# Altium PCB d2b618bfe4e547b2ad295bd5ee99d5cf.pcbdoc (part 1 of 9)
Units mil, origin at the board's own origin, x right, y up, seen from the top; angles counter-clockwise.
Board outline 5129 x 4161 mil, 8 copper layers (Top Layer, GND1, 内层2, VCC, 内层4, Inner5, GND2, Bottom Layer); 491 components, 452 nets, 2562 pads, 1124 vias.
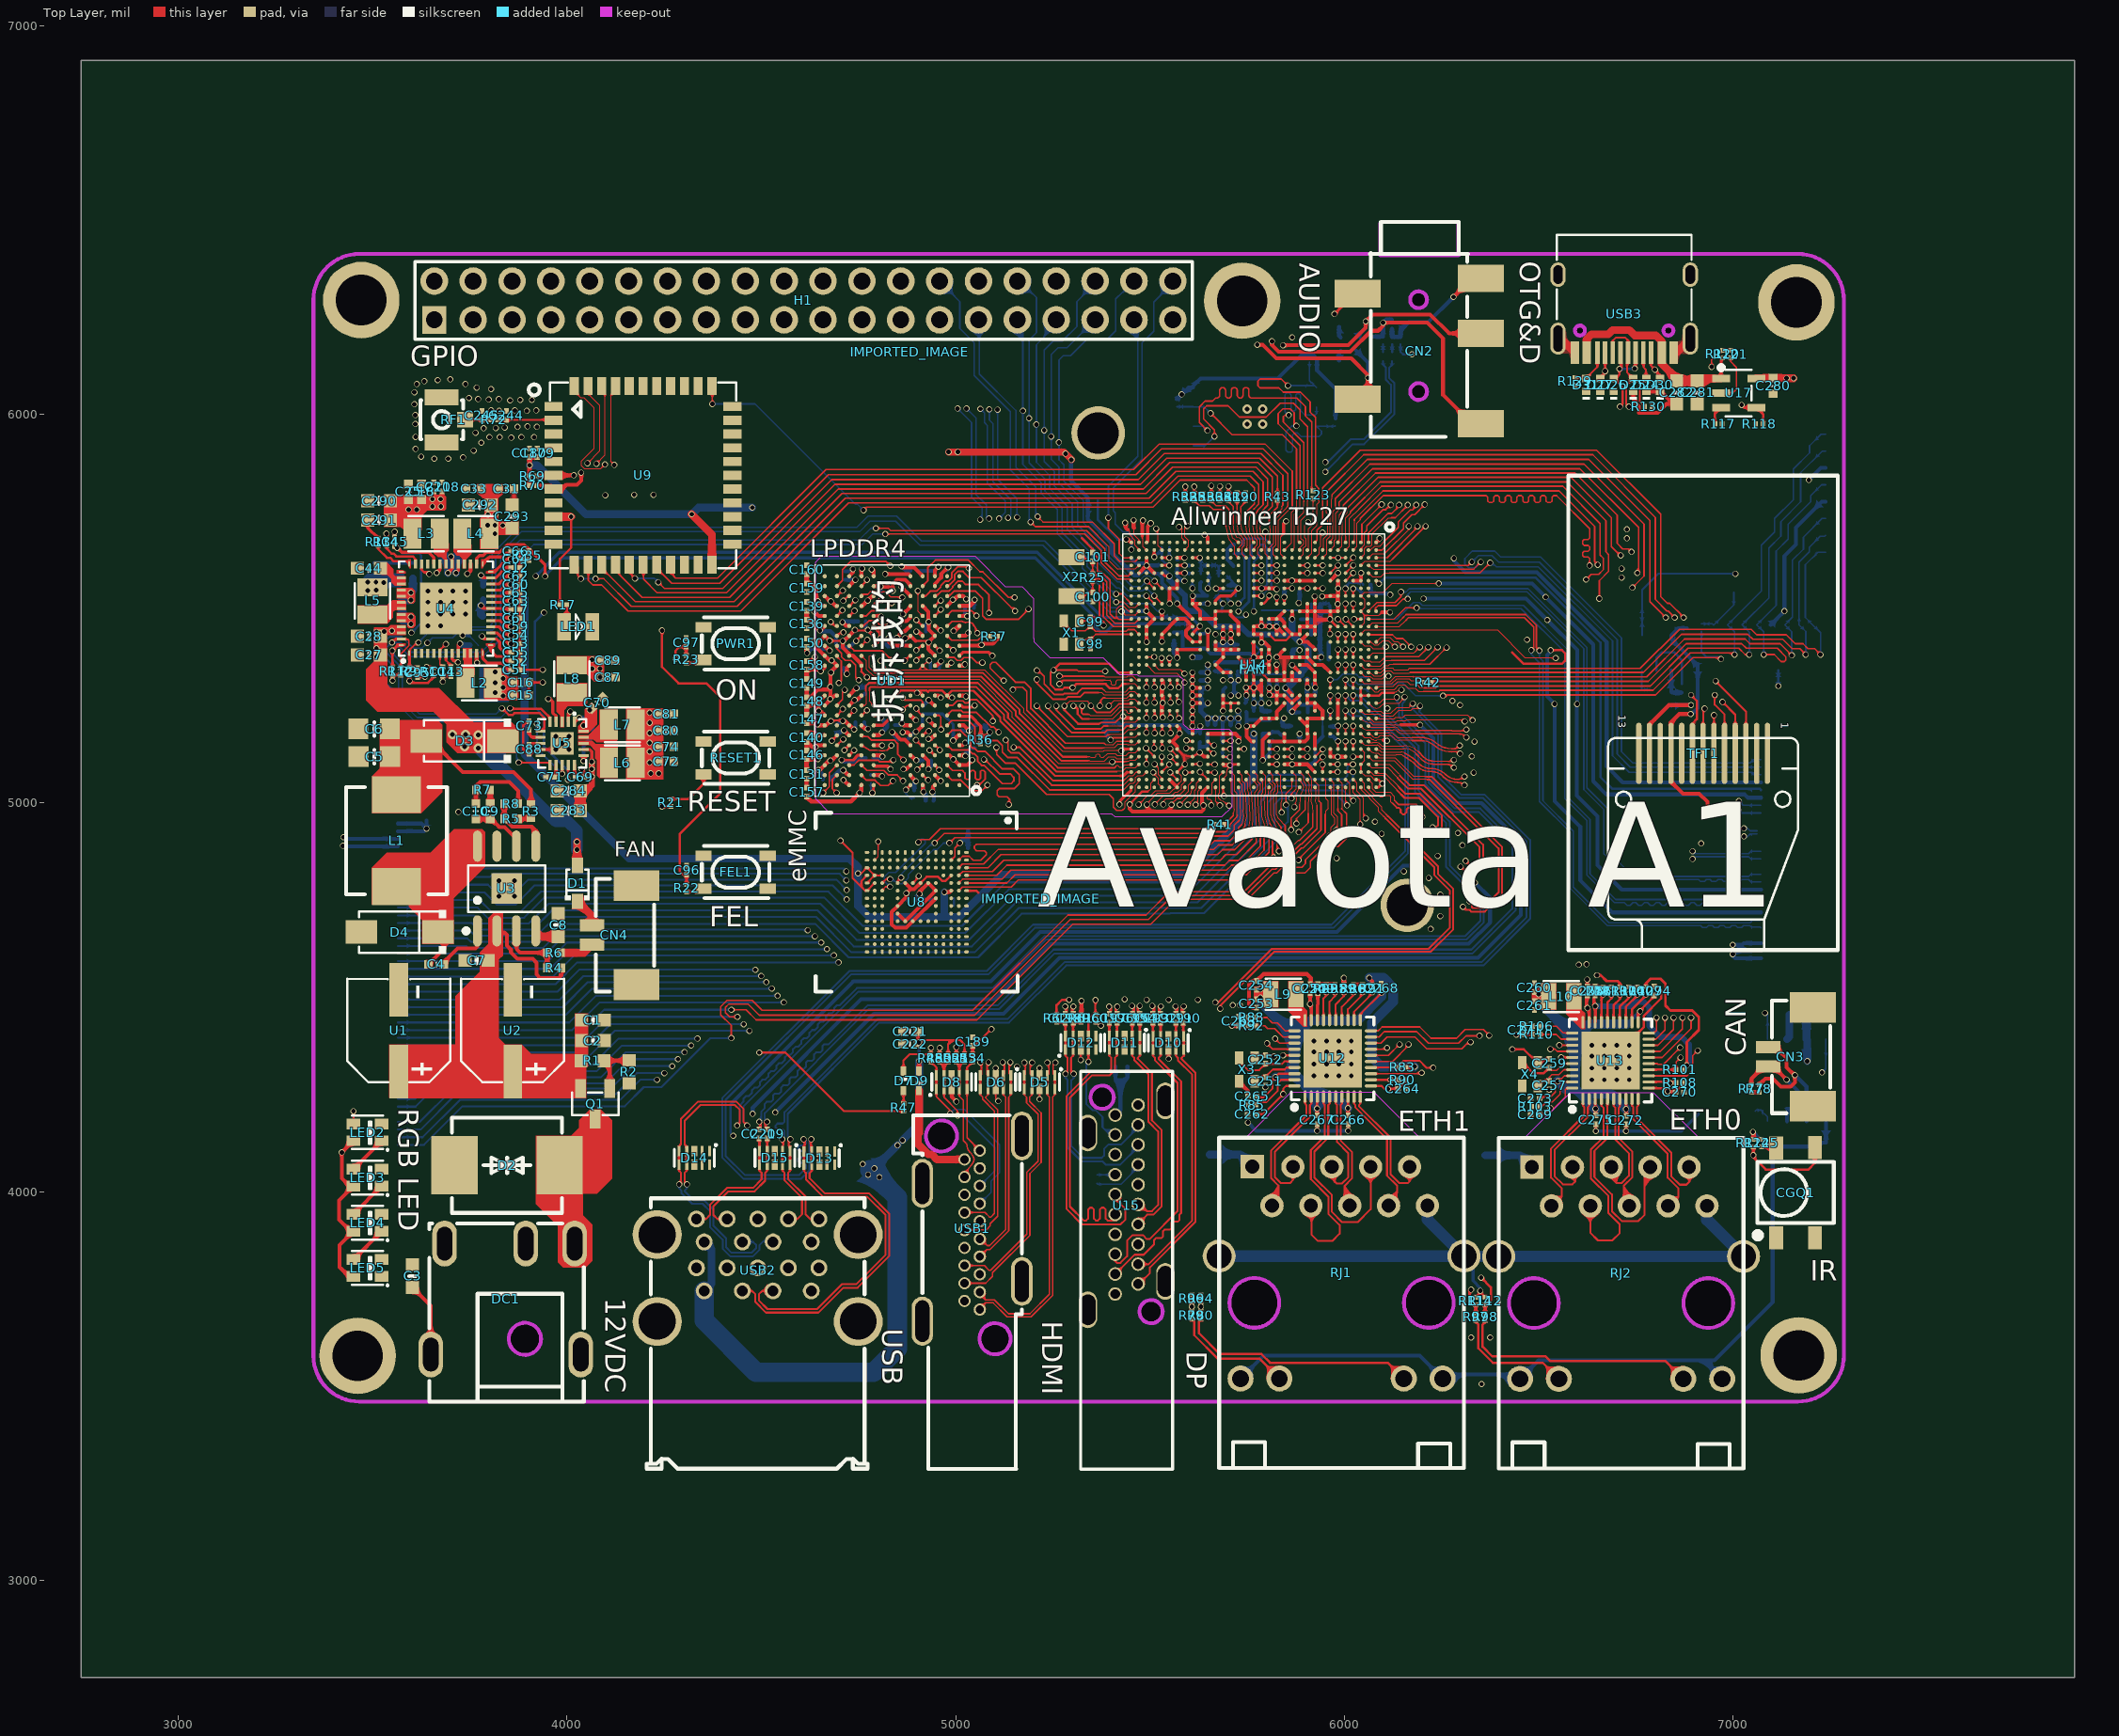
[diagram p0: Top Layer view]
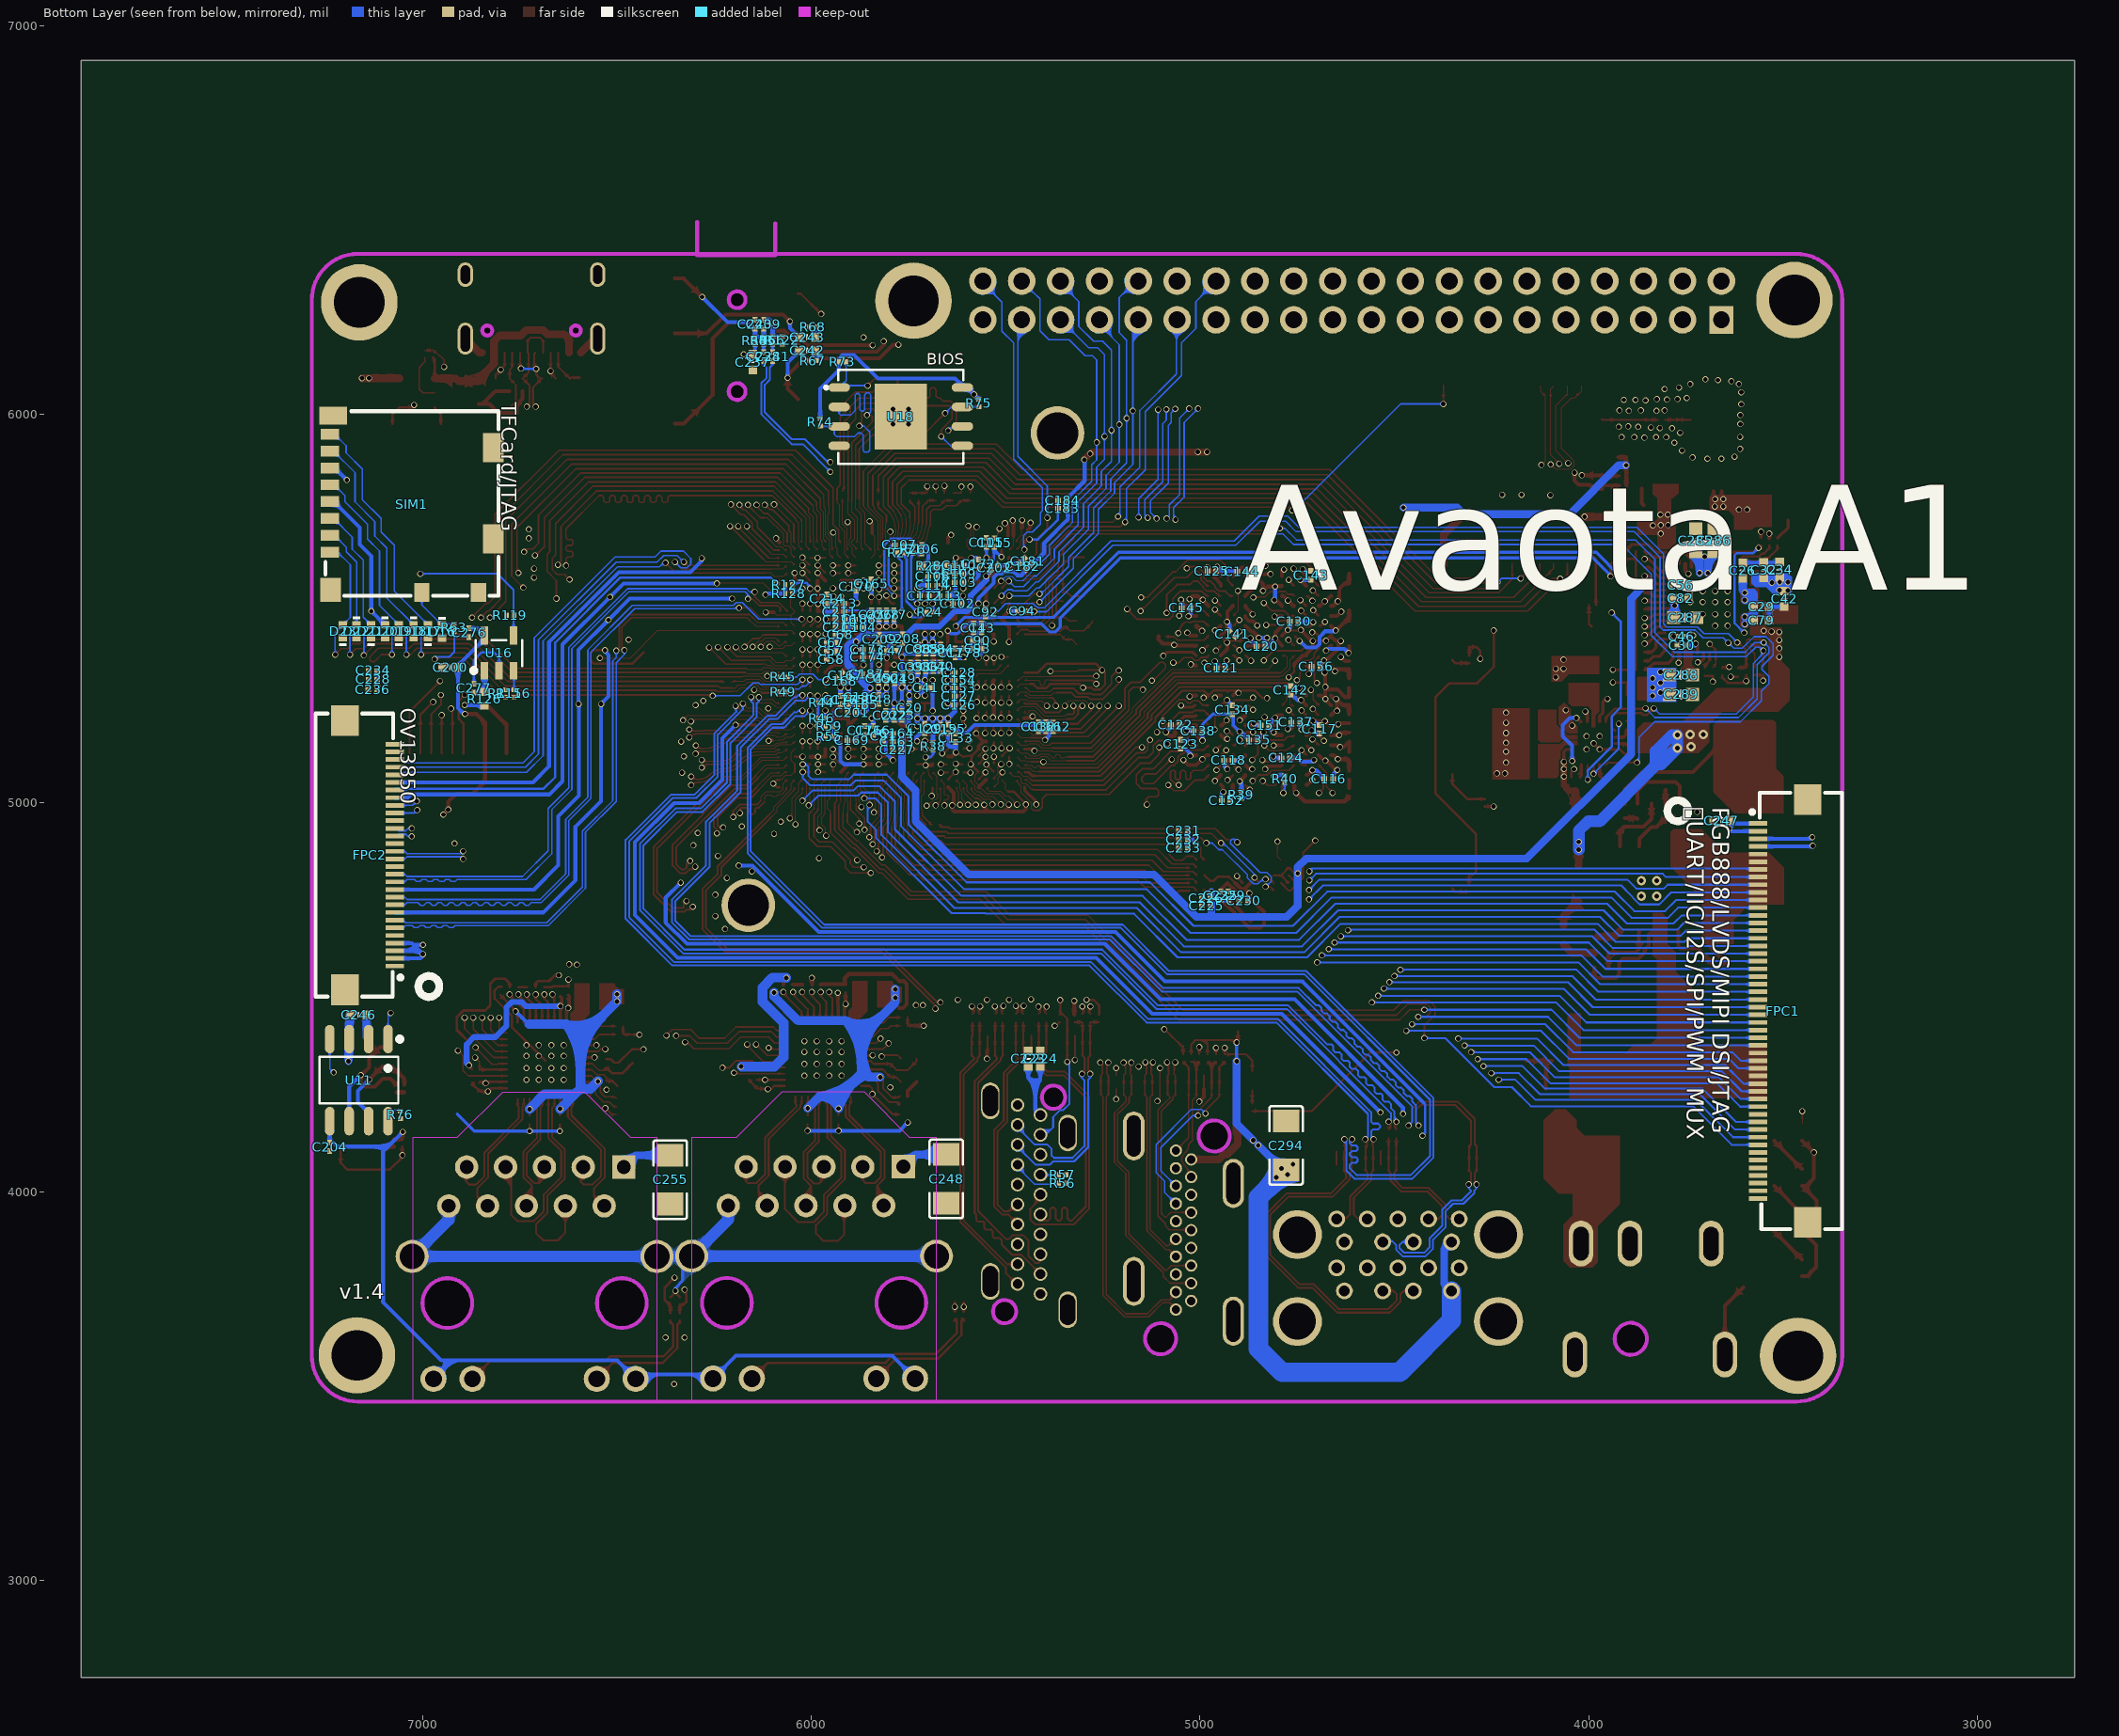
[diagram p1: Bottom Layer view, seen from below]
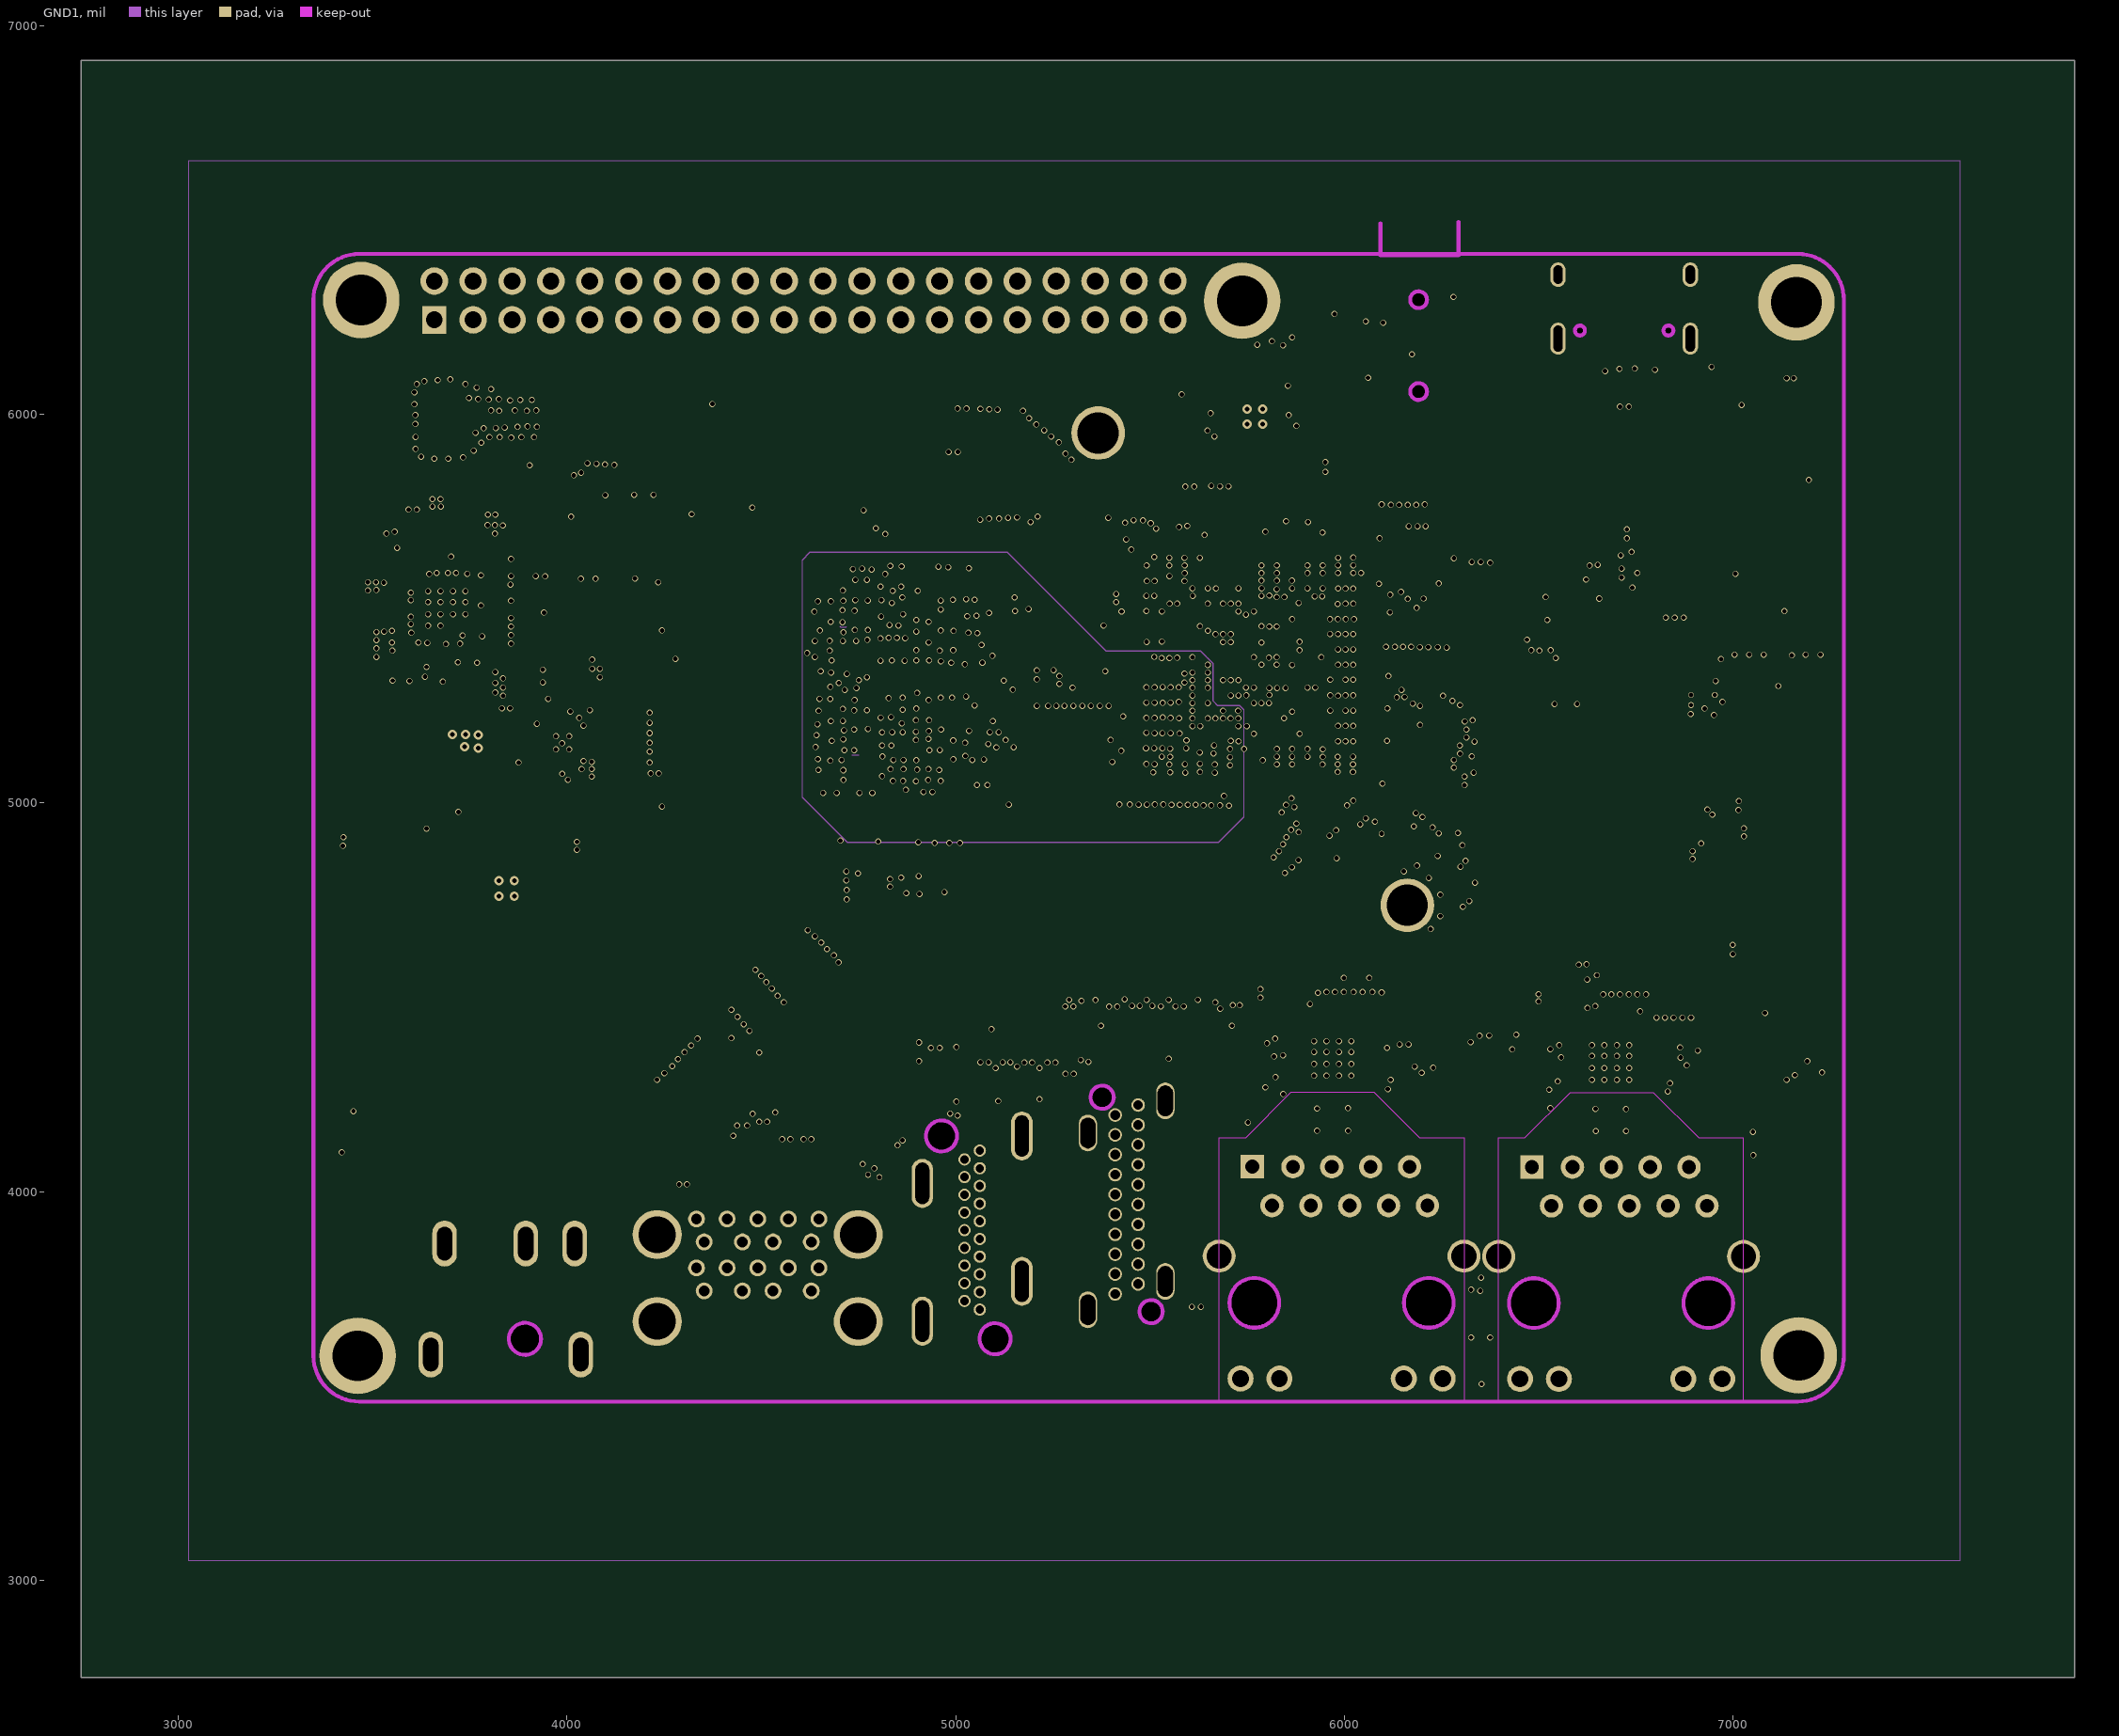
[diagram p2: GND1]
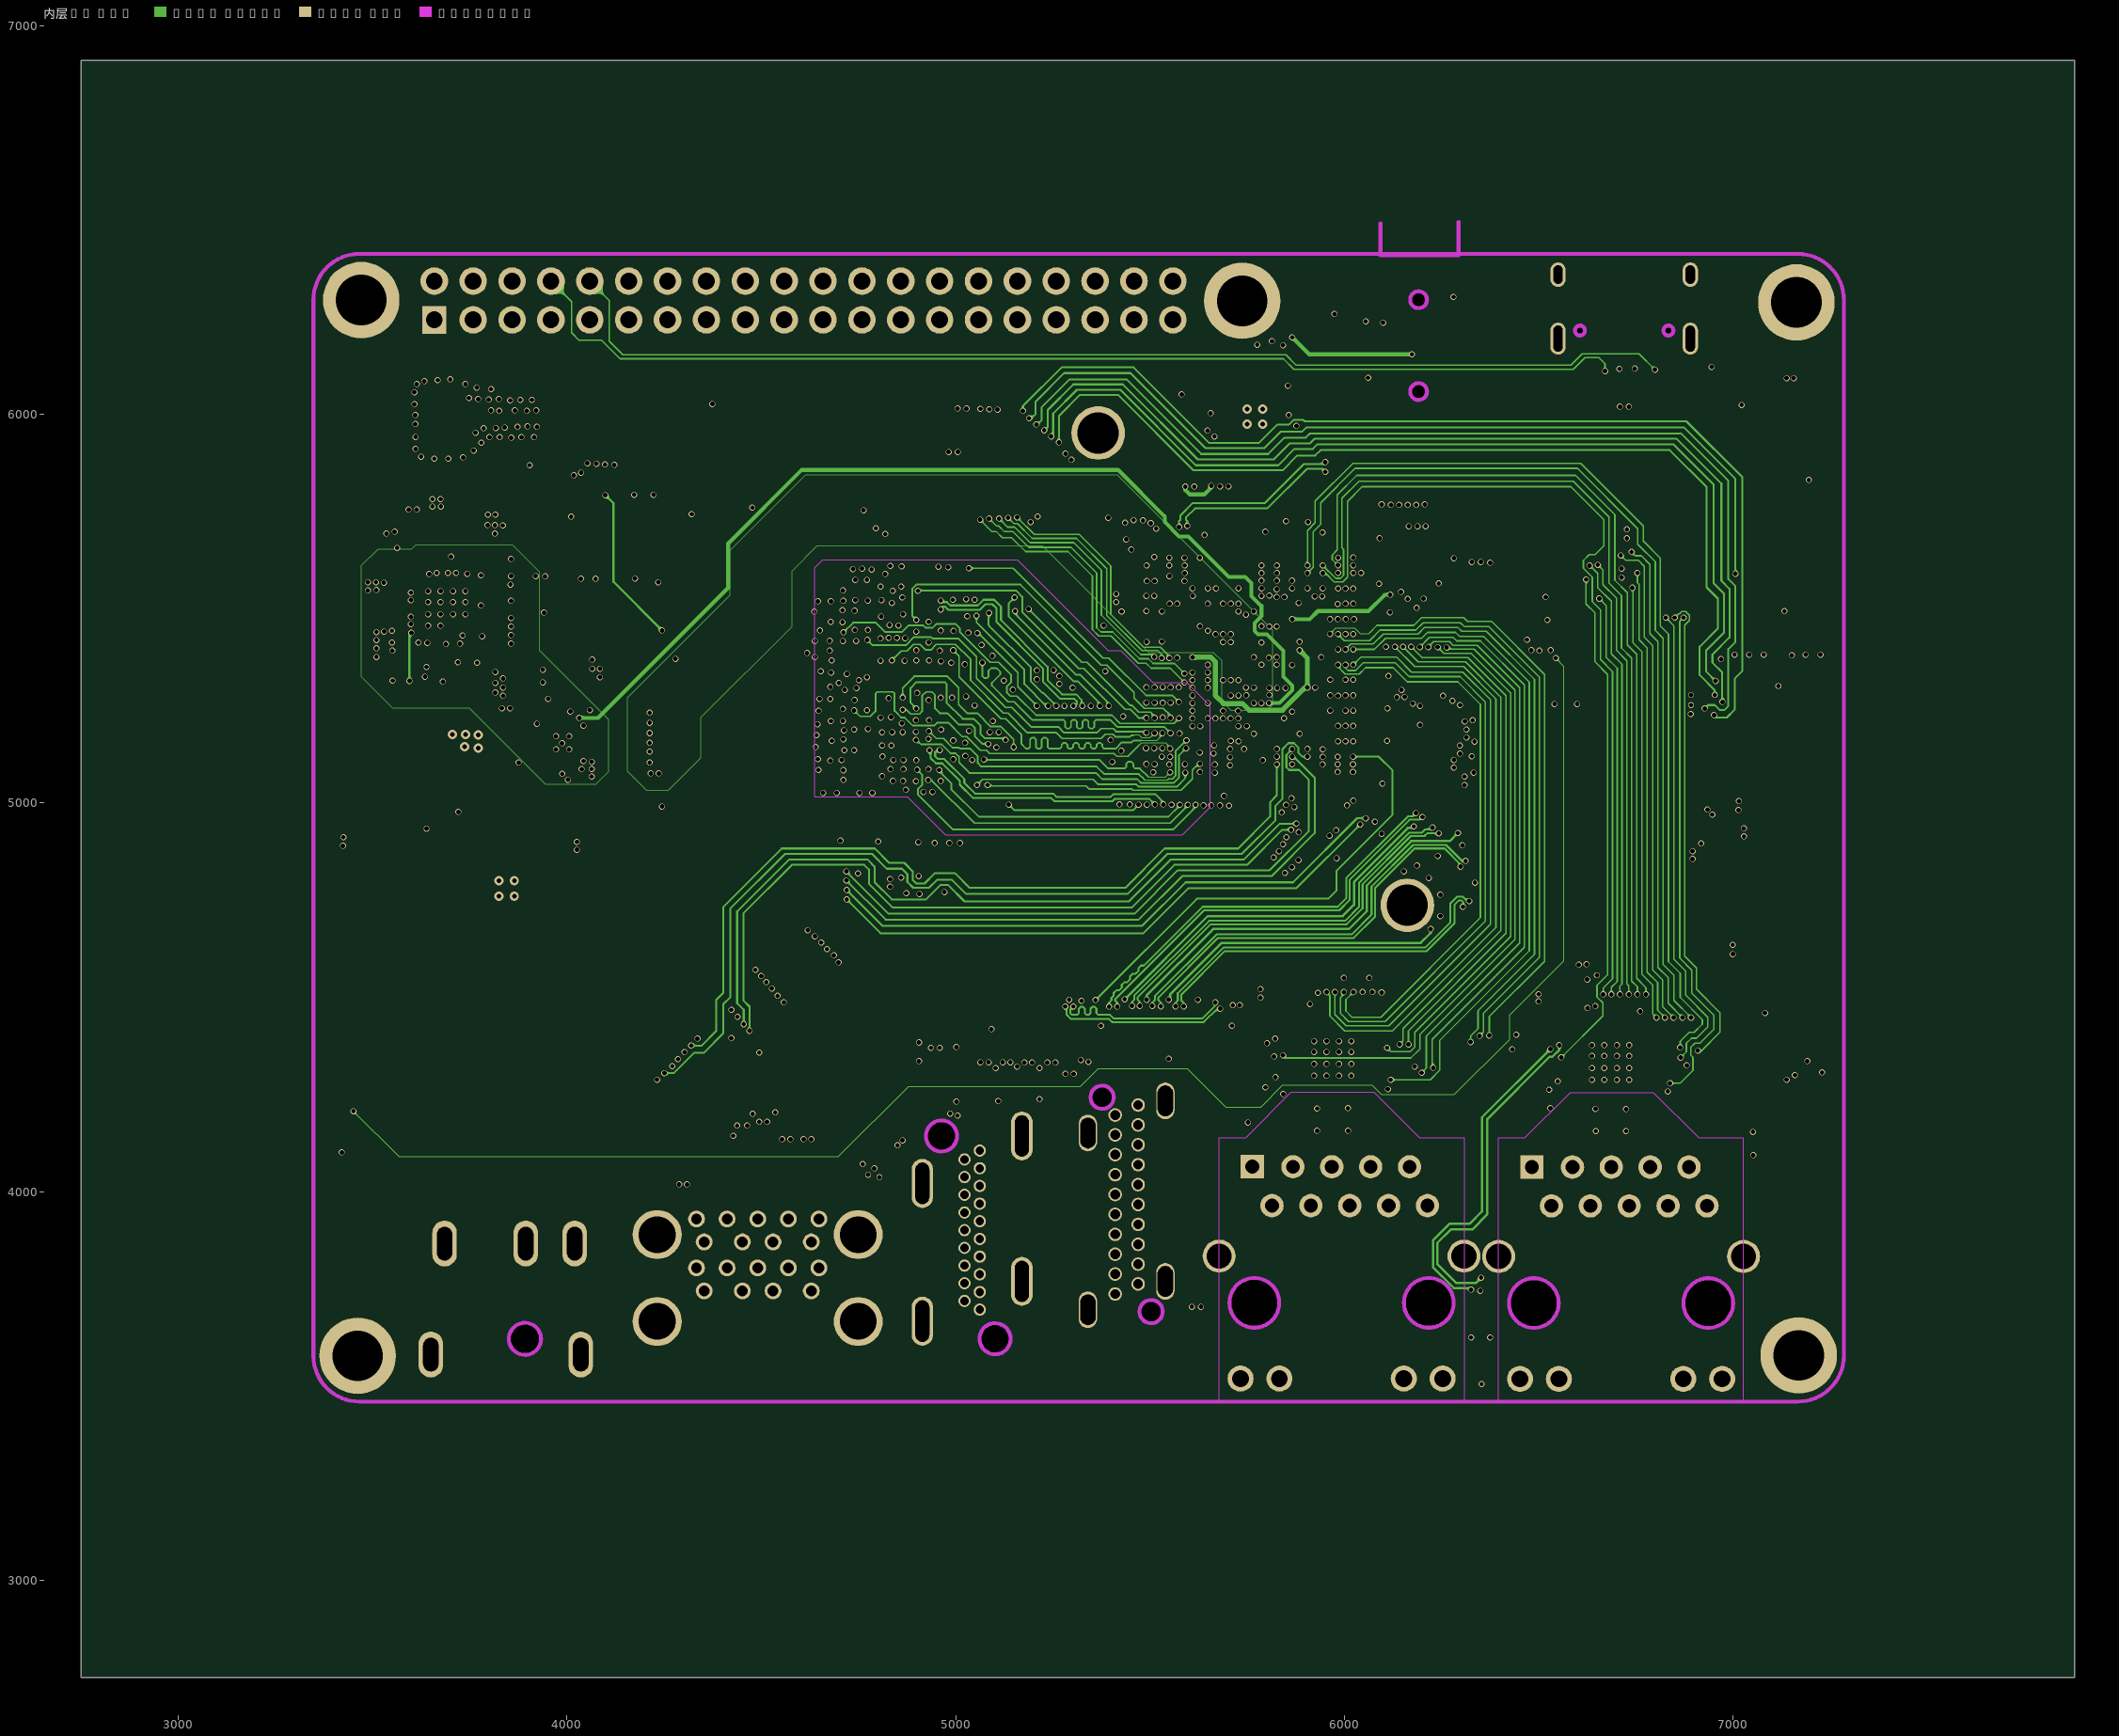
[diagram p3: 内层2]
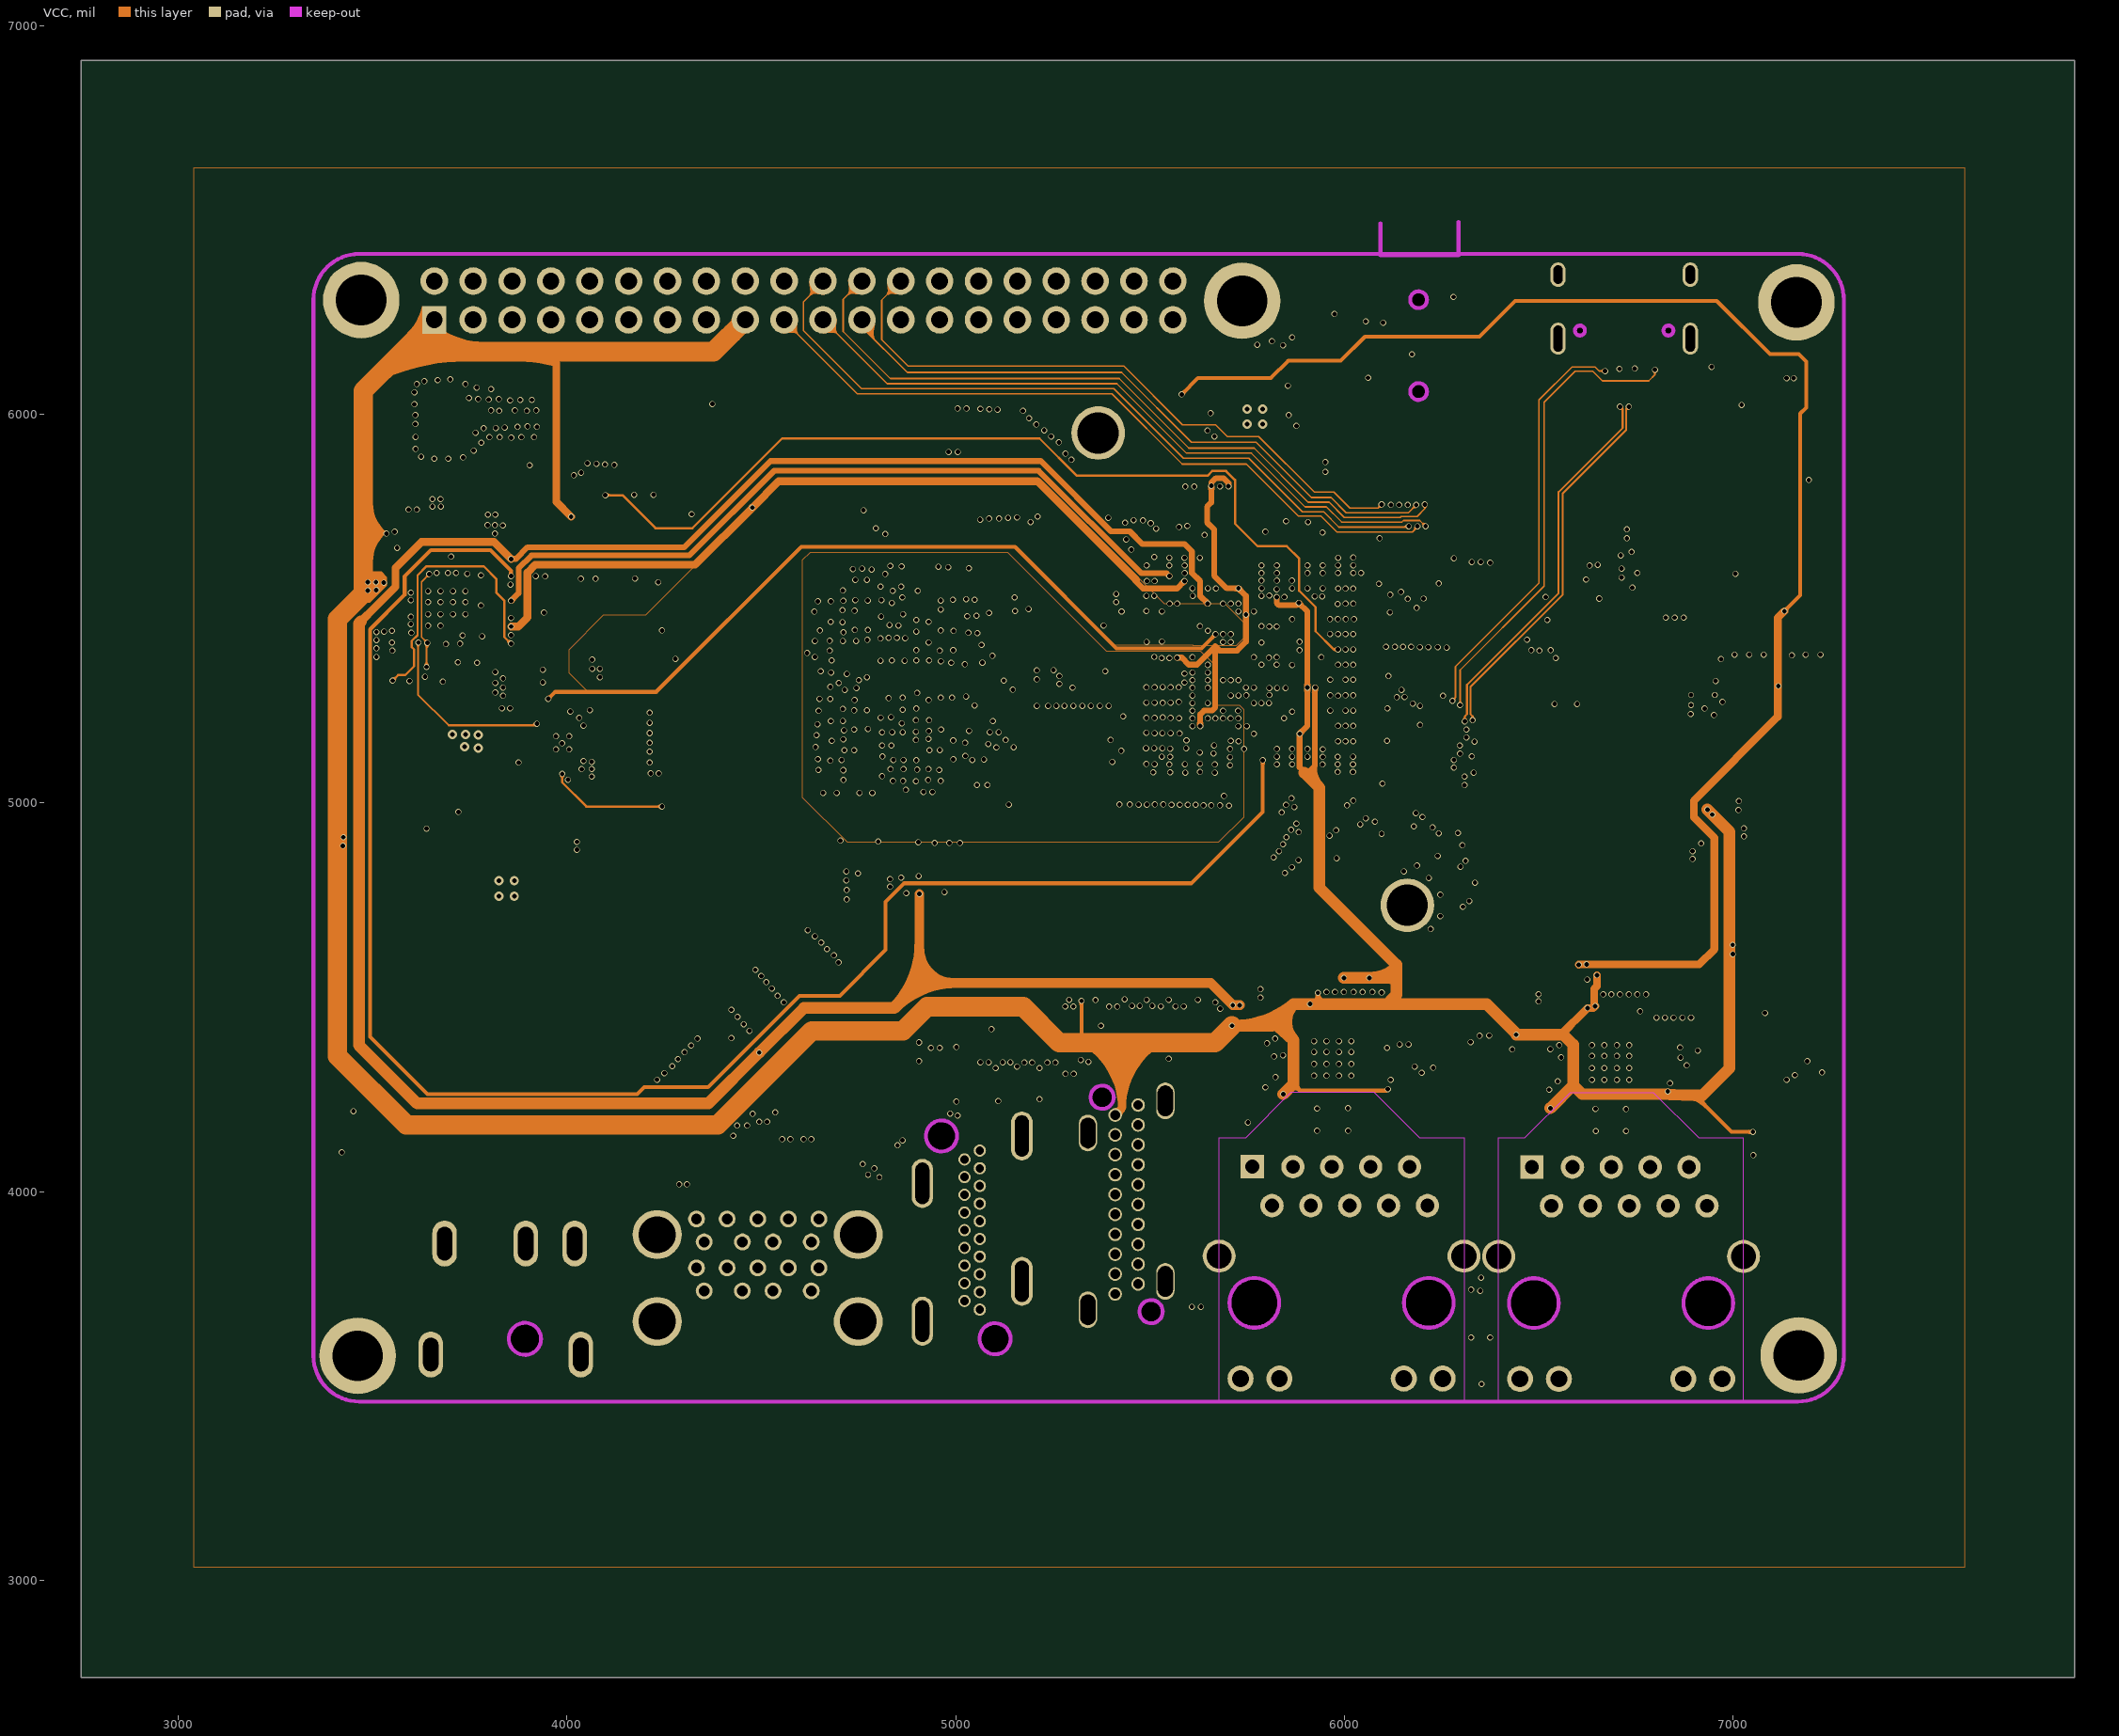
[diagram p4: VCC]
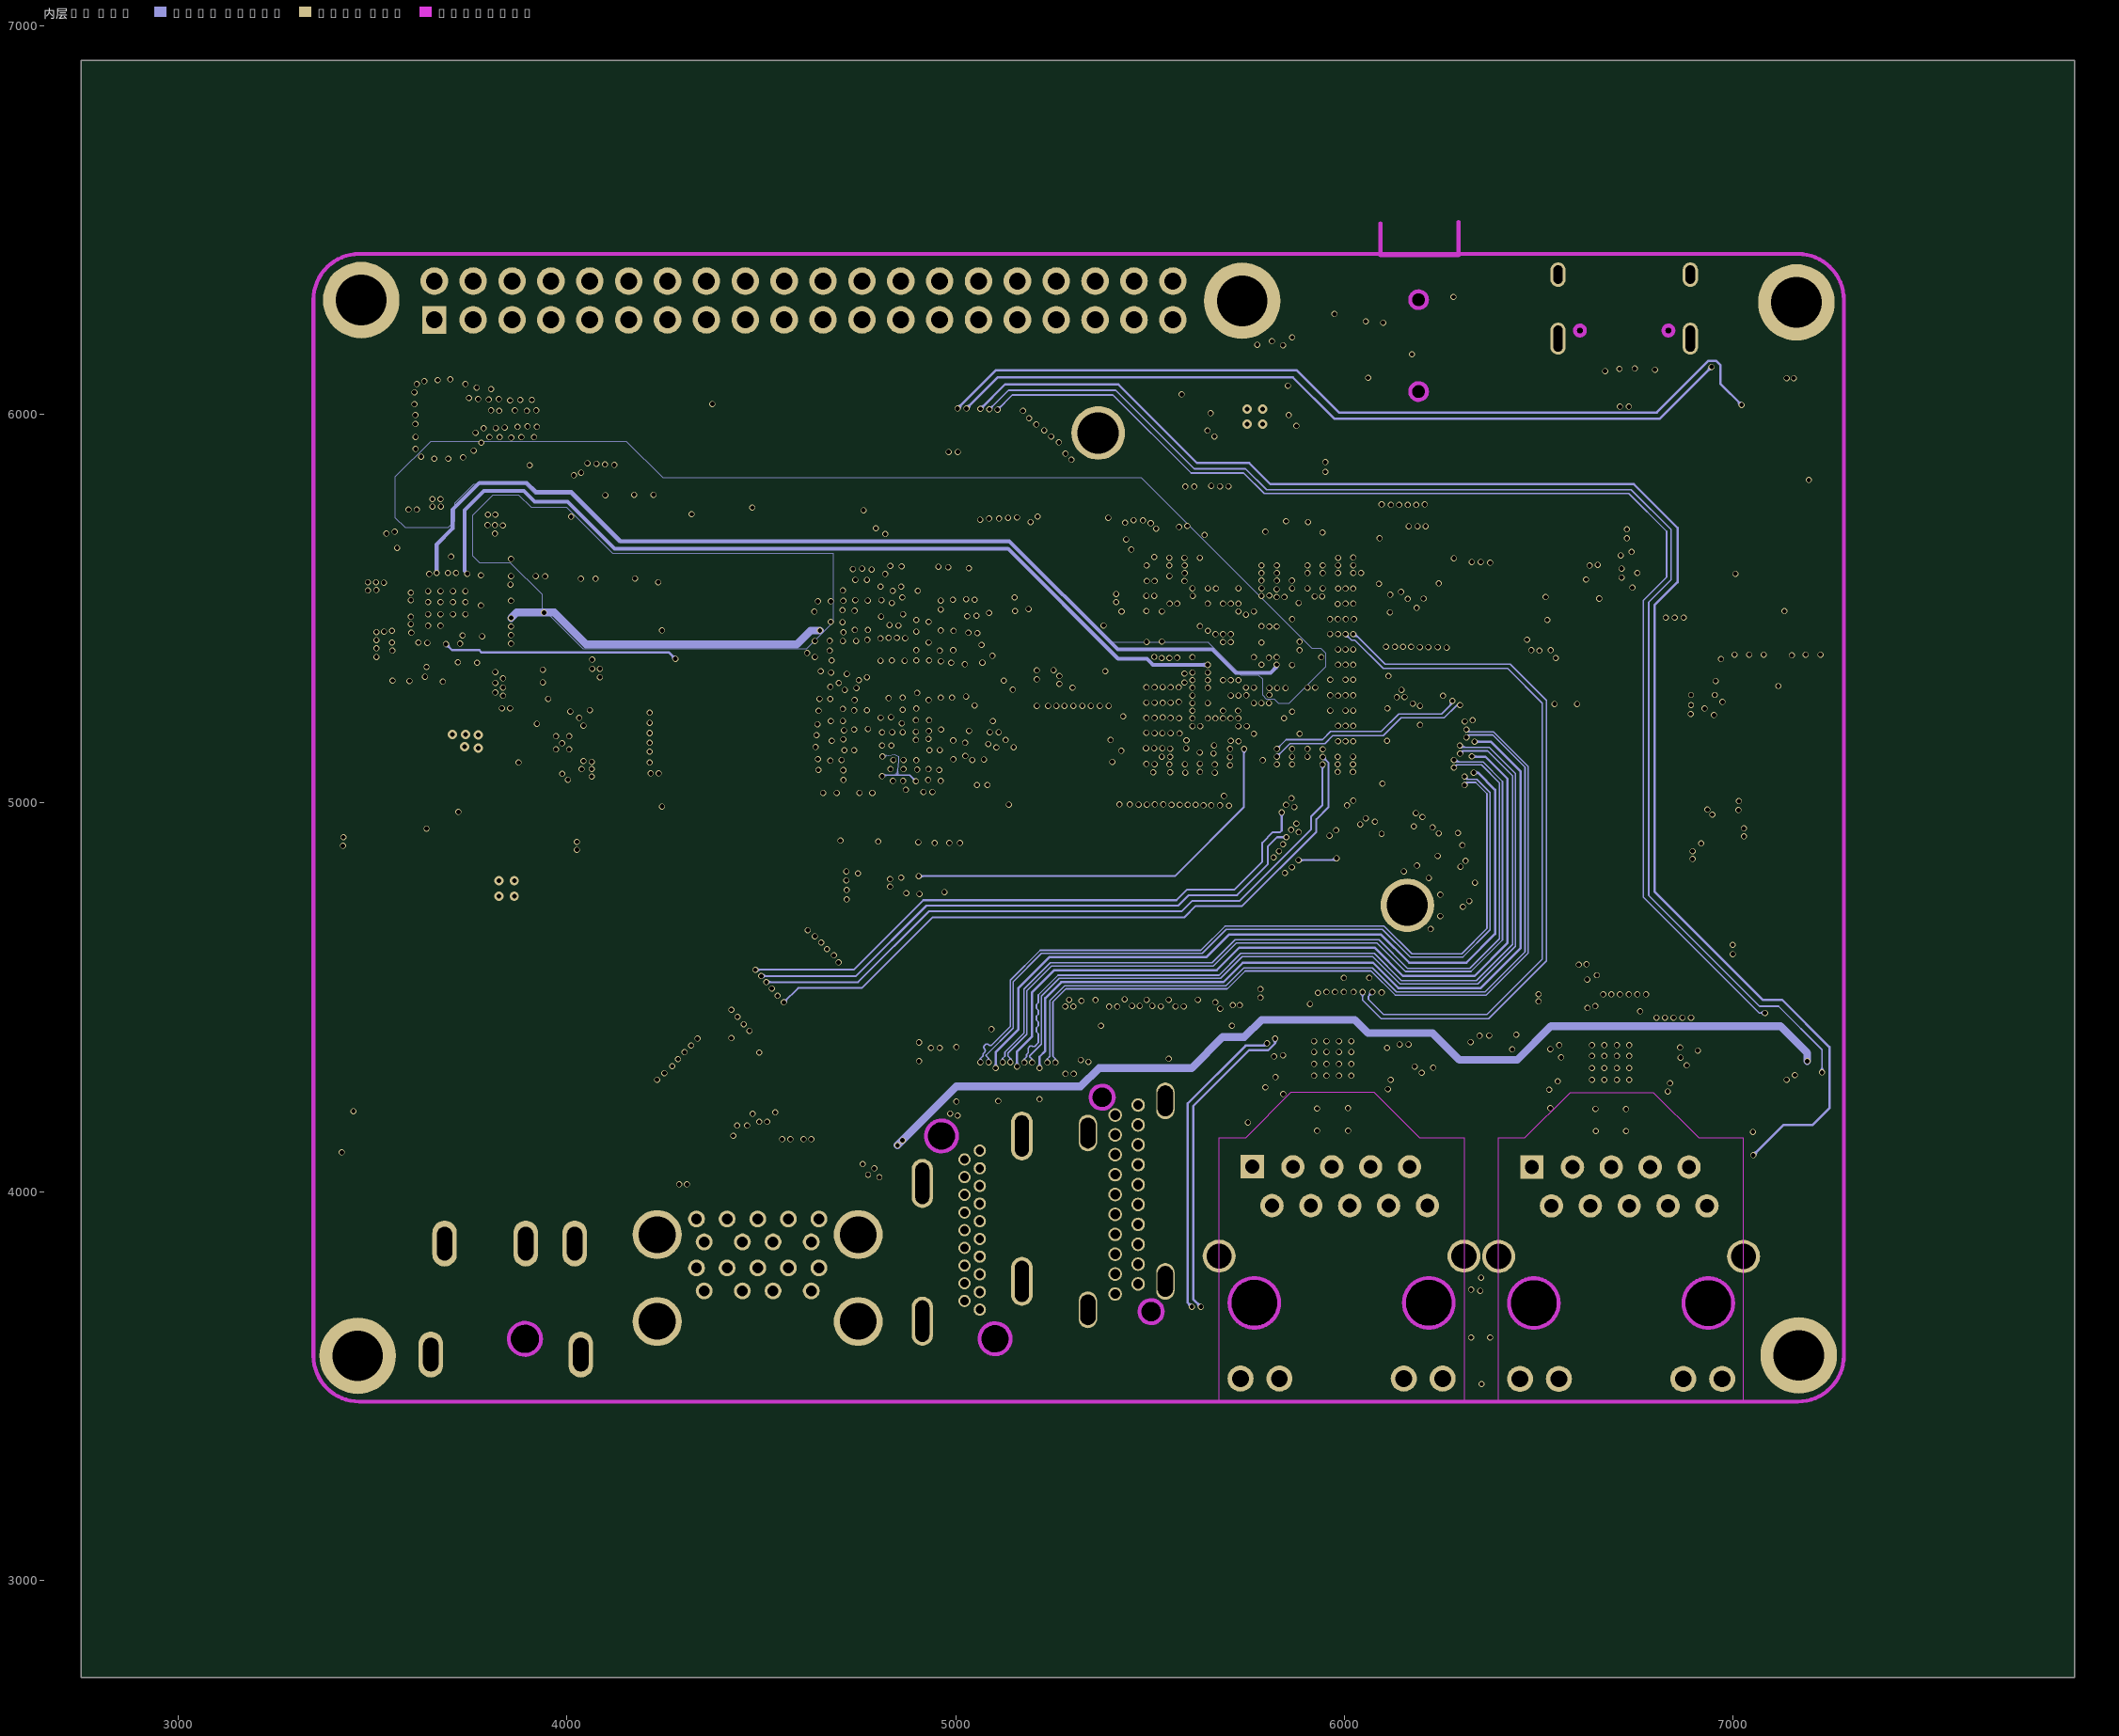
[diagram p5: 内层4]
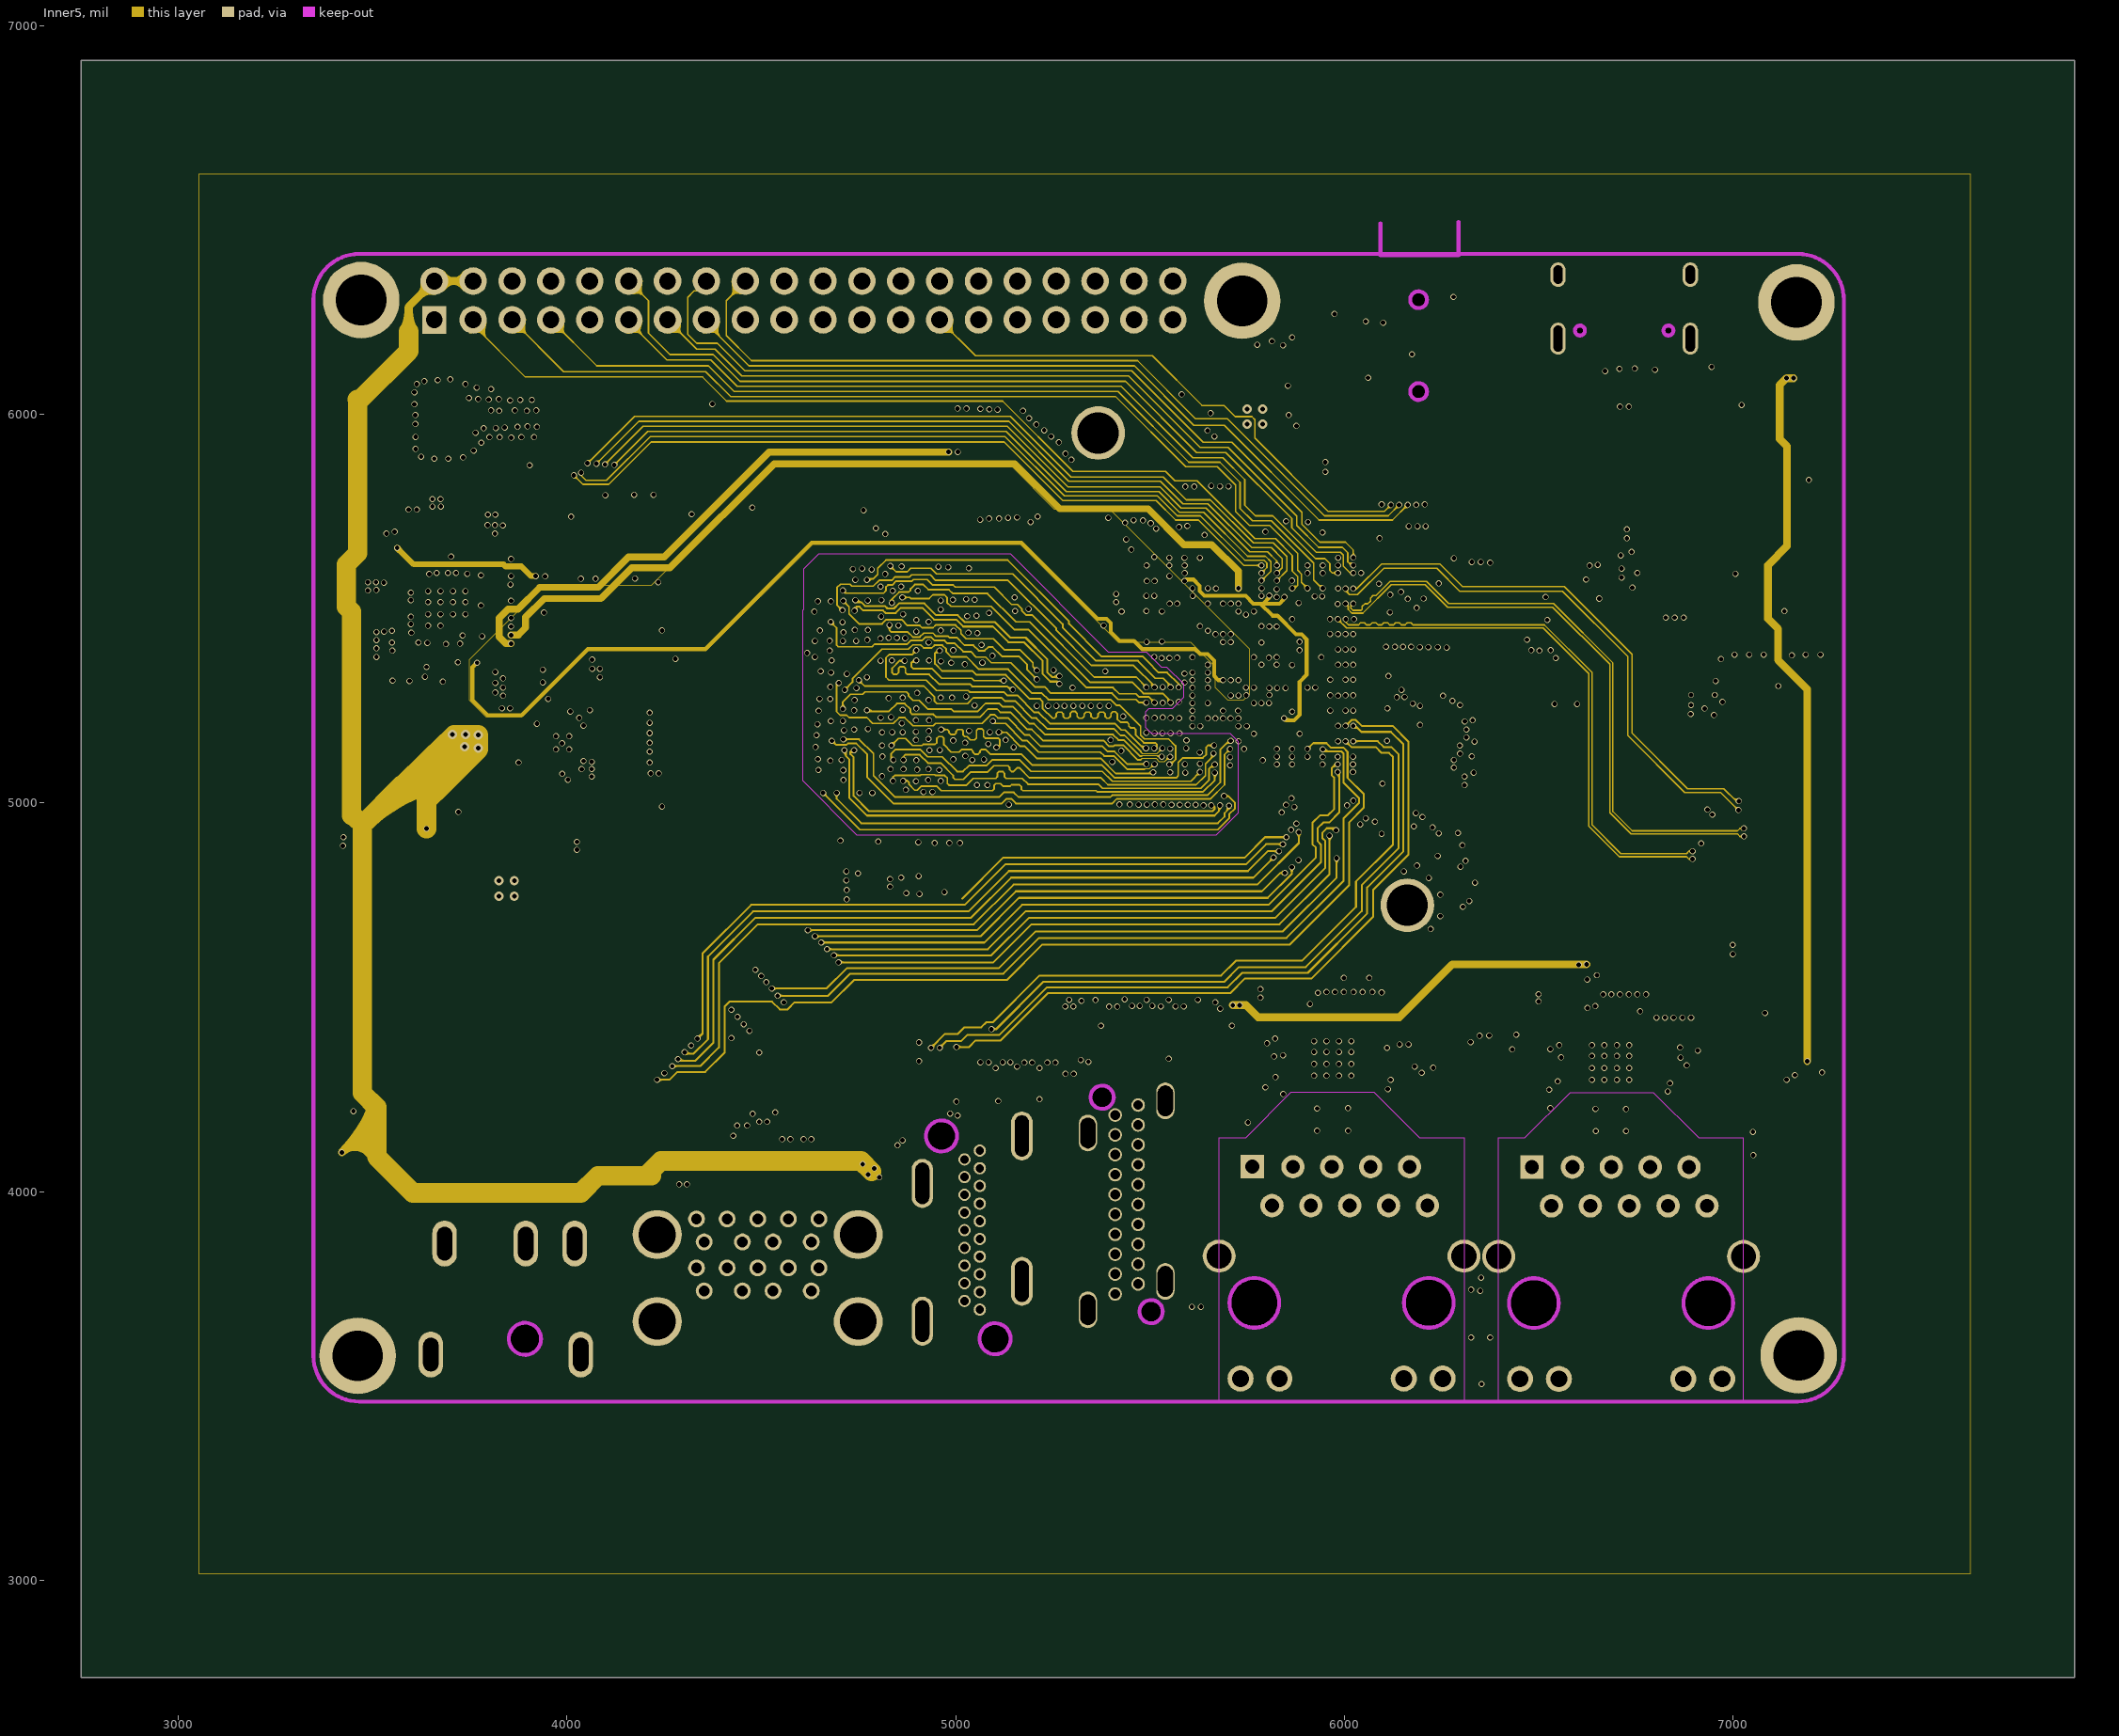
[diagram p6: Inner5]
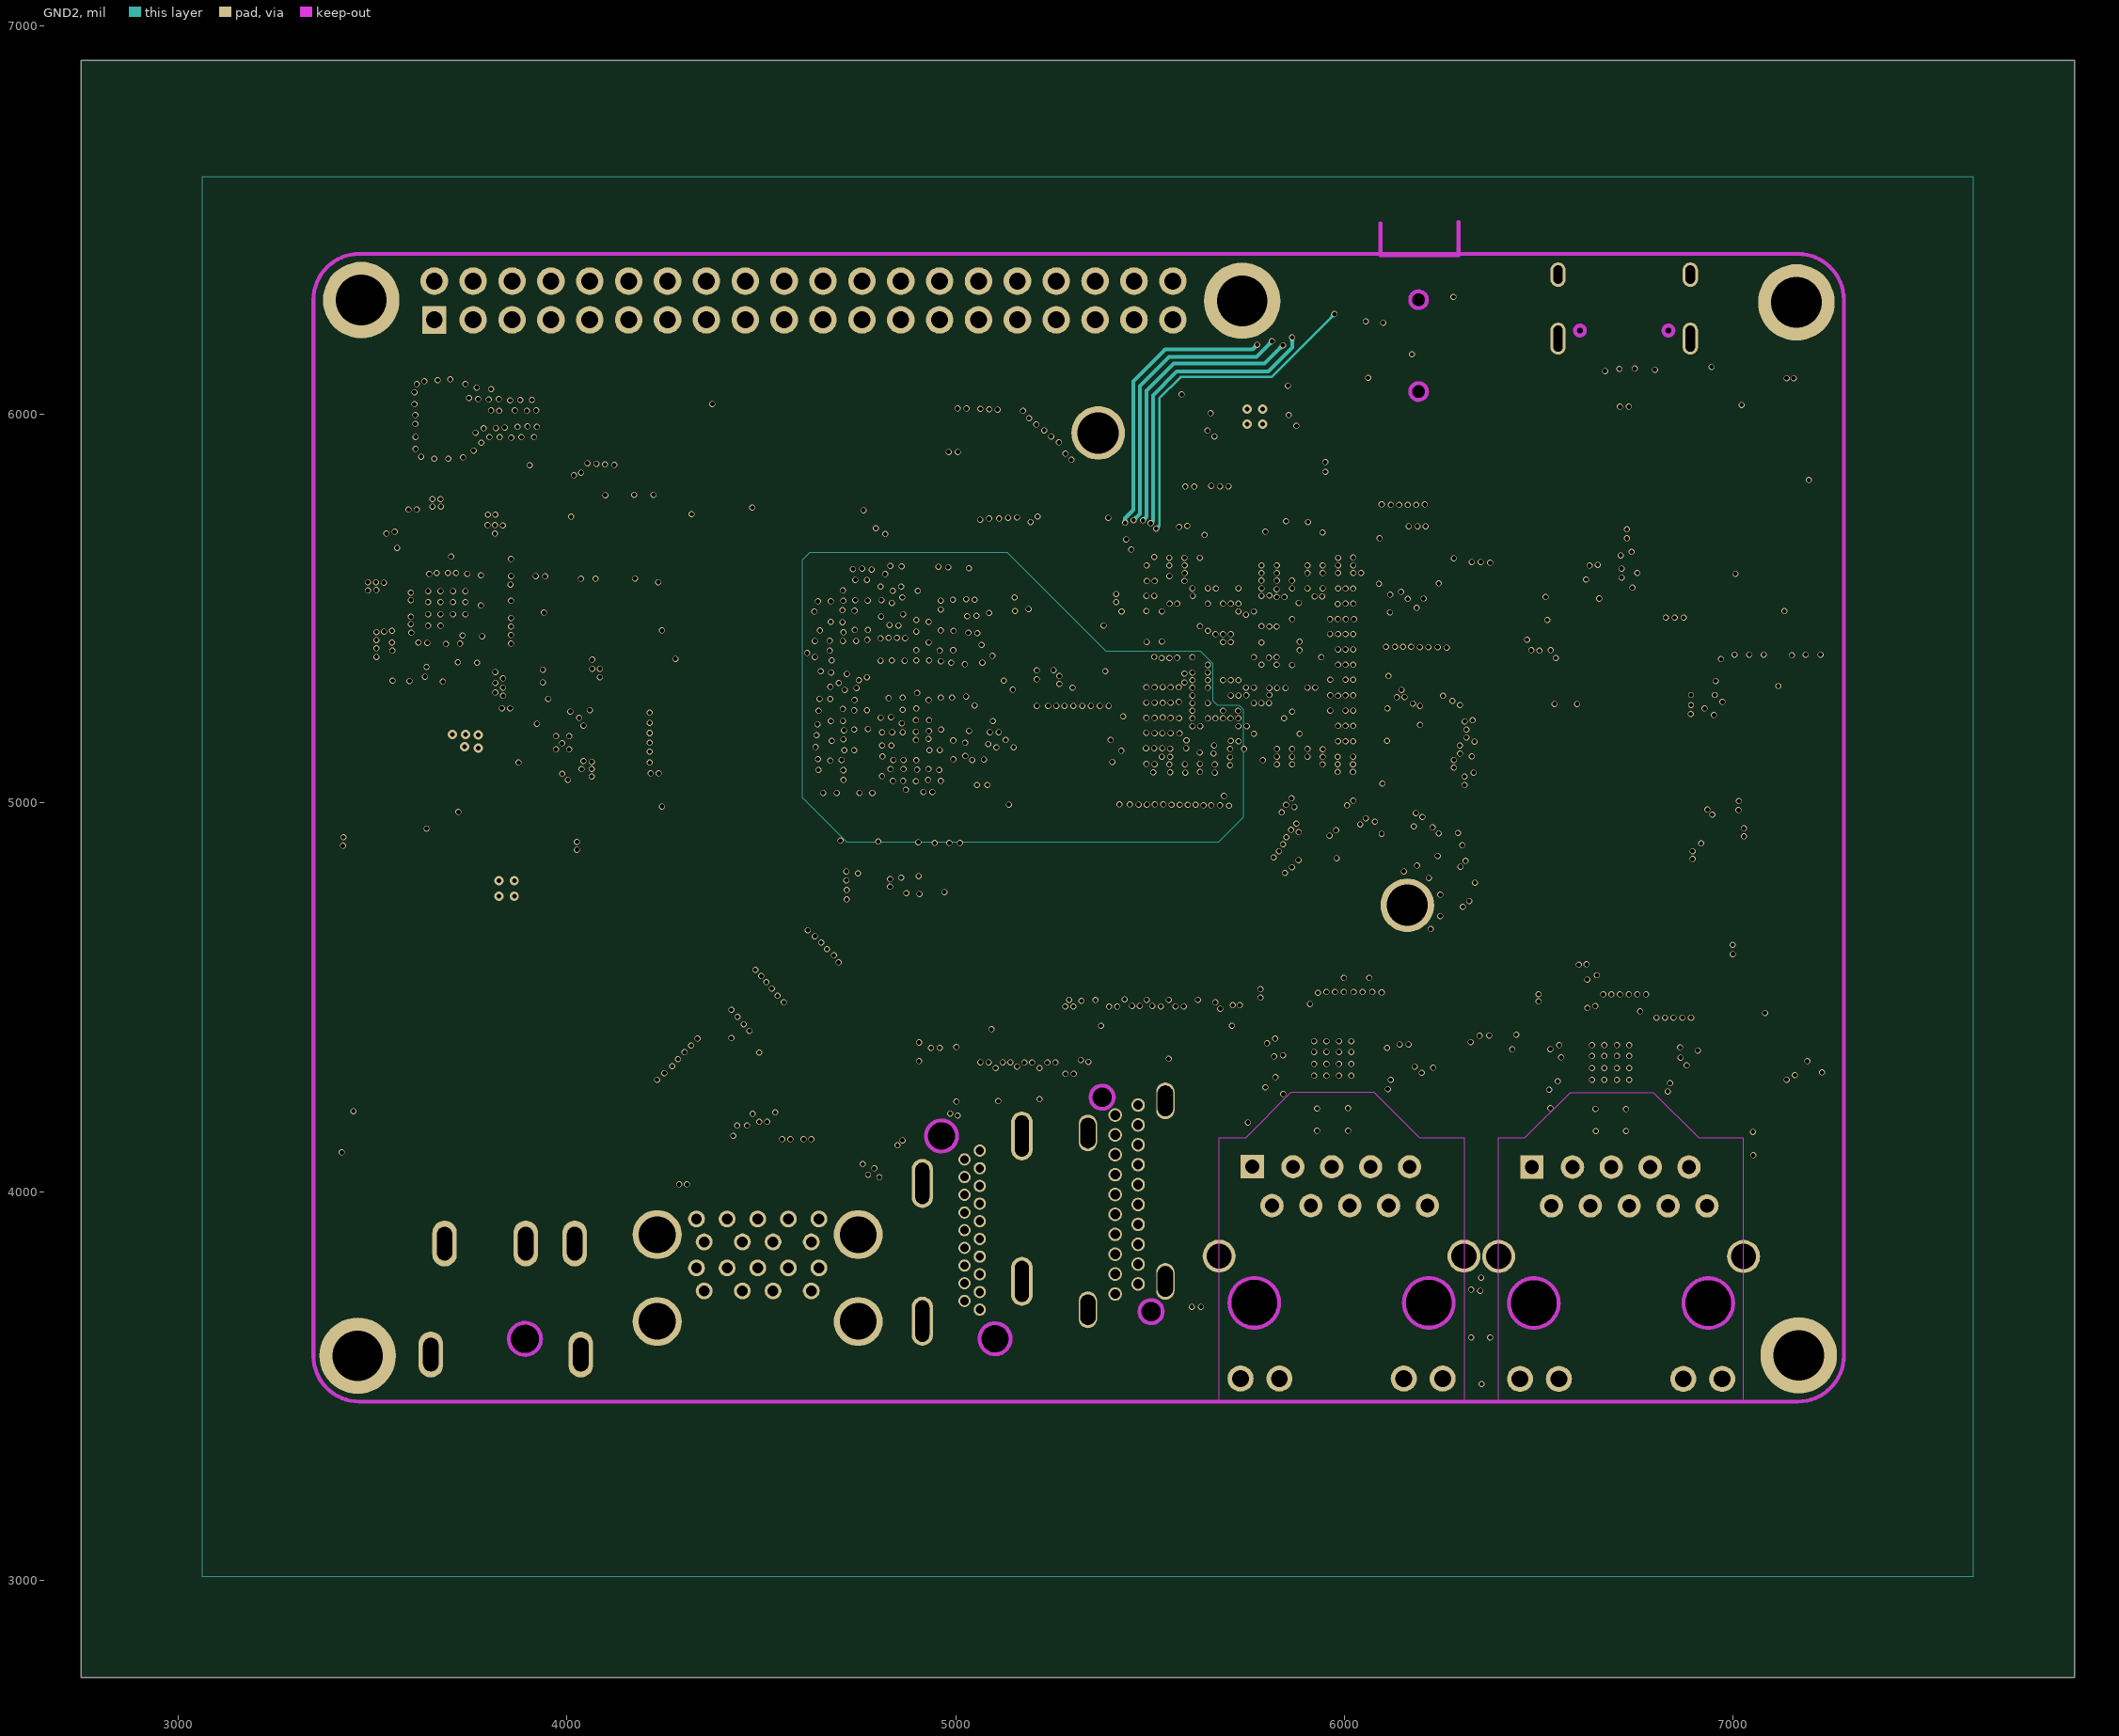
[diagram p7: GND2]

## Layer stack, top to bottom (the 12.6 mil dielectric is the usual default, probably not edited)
Top Layer: signal copper (thickness not stored)
Dielectric: dielectric 12.6, FR-4, Dk 4.8
GND1: signal copper (thickness not stored)
Dielectric: dielectric 12.6, FR-4, Dk 4.8
内层2: signal copper (thickness not stored)
Dielectric: dielectric 12.6, FR-4, Dk 4.8
VCC: signal copper (thickness not stored)
Dielectric: dielectric 12.6, FR-4, Dk 4.8
内层4: signal copper (thickness not stored)
Dielectric: dielectric 12.6, FR-4, Dk 4.8
Inner5: signal copper (thickness not stored)
Dielectric: dielectric 12.6, FR-4, Dk 4.8
GND2: signal copper (thickness not stored)
Dielectric: dielectric 12.6, FR-4, Dk 4.8
Bottom Layer: signal copper (thickness not stored)

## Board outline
7879,2750 2750,2750 2750,6911 7879,6911

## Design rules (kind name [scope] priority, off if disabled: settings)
Clearance safeClearance [All] p1: gap=7 ignorepadtopadclearanceinfootprint=FALSE except(3: Track-Track Track-SMDPad SMDPad-SMDPad Track-THPad SMDPad-THPad THPad-THPad Track-Via SMDPad-Via THPad-Via Via-Via Track-Hole SMDPad-Hole THPad-Hole Via-Hole; 3.5: Track-Fill SMDPad-Fill THPad-Fill Via-Fill Fill-Fill Track-Region SMDPad-Region THPad-Region Via-Region Fill-Region Region-Region Track-Poly SMDPad-Poly THPad-Poly Via-Poly Fill-Poly Region-Poly Poly-Poly Track-Text SMDPad-Text THPad-Text Via-Text Fill-Text Region-Text Poly-Text Text-Text SMDPad-Sheet THPad-Sheet Fill-Hole Region-Hole Poly-Hole Text-Hole Sheet-Hole; 11.8: Track-Sheet Via-Sheet Fill-Sheet Region-Sheet Poly-Sheet Text-Sheet)
DiffPairsRouting differentialPair [All] p1: maxuncoupledlength=50 minlimit=0 maxlimit=4 mostfreqgap=4 toplayer_minwidth=3 toplayer_prefwidth=10 toplayer_maxwidth=100 bottomlayer_minwidth=3 bottomlayer_prefwidth=10 bottomlayer_maxwidth=100 midlayer1_minwidth=3 midlayer1_prefwidth=10 midlayer1_maxwidth=100 midlayer2_minwidth=3 midlayer2_prefwidth=10 midlayer2_maxwidth=100 midlayer3_minwidth=3 midlayer3_prefwidth=10 midlayer3_maxwidth=100 midlayer4_minwidth=3 midlayer4_prefwidth=10 midlayer4_maxwidth=100 midlayer5_minwidth=3 midlayer5_prefwidth=10 midlayer5_maxwidth=100 midlayer6_minwidth=3 midlayer6_prefwidth=10 midlayer6_maxwidth=100
PasteMaskExpansion pasteMaskExpansion [All] p1: expansion=0
PlaneConnect innerPlane [All] p1: planeconnectstyle=Relief reliefexpansion=20 reliefentries=4 reliefconductorwidth=10 reliefairgap=10
PolygonConnect copperRegion [All] p1: connectstyle=Relief reliefentries=4 reliefconductorwidth=10 polygonreliefangle="90 Angle" airgapwidth=10
PolygonConnect TBCopper [All] p1: connectstyle=Relief reliefentries=4 reliefconductorwidth=6 polygonreliefangle="90 Angle" airgapwidth=6
PolygonConnect DRAMCopper [All] p1: connectstyle=Relief reliefentries=4 reliefconductorwidth=4 polygonreliefangle="90 Angle" airgapwidth=4
RoutingVias viaSize [All] p1: viastyle="Through Hole" holewidth=7.9 minholewidth=7.9 maxholewidth=236.2 width=17.7 minwidth=15.7 maxwidth=393.7
SolderMaskExpansion solderMaskExpansion [All] p1: useseparateexpansions=TRUE expansion=4 expansionbottom=4
Width trackWidth [All] p1: maxlimit=100 minlimit=3 preferedwidth=4

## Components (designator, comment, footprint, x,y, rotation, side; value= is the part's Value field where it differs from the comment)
C1 "CAP_0603" C0603-NSK 4067,4441.54 r180 top
C2 "CAP_0603" C0603-NSK 4067,4388.54 r180 top
C3 "CAP_0603" C0603-NSK 3603,3783 r270 top
C4 "CAP_0402" c0402-nsk 3664,4585 r180 top
C5 "CAP_0805" "C0805 NSK" 3504.85,5119.18 r0 top
C6 "CAP_0805" "C0805 NSK" 3504.4,5190.55 r0 top
C7 "CAP_0603" C0603-NSK 3768,4595 r0 top
C8 "CAP_0603" C0603-NSK 3978,4686 r270 top
C9 "CAP_0402" c0402-nsk 3803,4979 r90 top
C10 "CAP_0402" c0402-nsk 3766,4979 r90 top
C11 "GRM033R60J104KE19D" "c0201 nsk" 3681,5338 r270 top
C12 "GRM033R61A105ME44D" "c0201 nsk" 3868,5606 r0 top
C13 "0201X225M6R3NT" "c0201 nsk" 5561.65,5450.18 r270 bottom
C14 "0201X225M6R3NT" "c0201 nsk" 5582.68,5450.35 r270 bottom
C15 "GRM155R60J226ME11D" c0402-nsk 3882.01,5277.28 r180 top
C16 "GRM155R60J226ME11D" c0402-nsk 3882.01,5310.28 r180 top
C17 "GRM033R61A105ME44D" "c0201 nsk" 3868,5498 r0 top
C18 "GRM155R60J226ME11D" c0402-nsk 3626.36,5800.65 r270 top
C19 "0201X225M6R3NT" "c0201 nsk" 5764,5320 r90 bottom
C20 "0201X225M6R3NT" "c0201 nsk" 5748,5245 r270 bottom
C21 "0201X225M6R3NT" "c0201 nsk" 5809,5225 r270 bottom
C22 "0201X225M6R3NT" "c0201 nsk" 5787,5225 r270 bottom
C23 "0201X225M6R3NT" "c0201 nsk" 5767,5225 r270 bottom
C24 "0201X225M6R3NT" "c0201 nsk" 5786,5320 r90 bottom
C25 "GRM155R60J226ME11D" c0402-nsk 3592.36,5800.65 r270 top
C26 "GRM155R60J226ME11D" c0402-nsk 3604,5598 r90 bottom
C27 "CL10A226MP8NUNE" C0603-NSK 3491,5381 r0 top
C28 "CL10A226MP8NUNE" C0603-NSK 3491,5429 r0 top
C29 "GRM155R60J226ME11D" c0402-nsk 3556.01,5504.72 r180 bottom
C30 "GRM033R61A105ME44D" "c0201 nsk" 3761,5406 r0 bottom
C31 "GRM155R60J226ME11D" c0402-nsk 3844,5809 r180 top
C32 "GRM155R60J226ME11D" c0402-nsk 3550,5599 r90 bottom
C33 "GRM155R60J226ME11D" c0402-nsk 3761,5809 r0 top
C34 "GRM155R60J226ME11D" c0402-nsk 3509,5600 r90 bottom
C35 "0201X225M6R3NT" "c0201 nsk" 3902,5637 r90 top
C36 "0201X225M6R3NT" "c0201 nsk" 5705.75,5350.75 r90 bottom
C37 "0201X225M6R3NT" "c0201 nsk" 5686.75,5350.75 r90 bottom
C38 "0201X225M6R3NT" "c0201 nsk" 5725.53,5350.11 r90 bottom
C39 "0201X225M6R3NT" "c0201 nsk" 5745.11,5349.97 r90 bottom
C40 "0201X225M6R3NT" "c0201 nsk" 5667,5351 r90 bottom
C41 "0201X225M6R3NT" "c0201 nsk" 5705,5297 r180 bottom
C42 "GRM155R60J226ME11D" c0402-nsk 3497,5525 r270 bottom
C43 "GRM033R61A105ME44D" "c0201 nsk" 3701.75,5337.72 r270 top
C44 "CL10A226MP8NUNE" C0603-NSK 3491,5604 r0 top
C45 "0201X225M6R3NT" "c0201 nsk" 3557,5672 r270 top
C46 "0201X225M6R3NT" "c0201 nsk" 3761,5429 r180 bottom
C47 "0201X225M6R3NT" "c0201 nsk" 5794,5392 r180 bottom
C48 "0201X225M6R3NT" "c0201 nsk" 5827,5266 r270 bottom
C49 "0201X225M6R3NT" "c0201 nsk" 5827,5321 r90 bottom
C50 "0201X225M6R3NT" "c0201 nsk" 5807,5321 r90 bottom
C51 "0201X225M6R3NT" "c0201 nsk" 3868,5343 r0 top
C52 "0201X225M6R3NT" "c0201 nsk" 3868,5366 r0 top
C53 "0201X225M6R3NT" "c0201 nsk" 3868,5410 r0 top
C54 "0201X225M6R3NT" "c0201 nsk" 3868,5432 r0 top
C55 "0201X225M6R3NT" "c0201 nsk" 3868,5388 r0 top
C56 "CL05A225KP5NSNC" c0402-nsk 3764,5560 r0 bottom
C57 "0201X225M6R3NT" "c0201 nsk" 5949,5391 r0 bottom
C58 "0201X225M6R3NT" "c0201 nsk" 5949,5369 r0 bottom
C59 "0201X225M6R3NT" "c0201 nsk" 3868,5454 r0 top
C60 "0201X225M6R3NT" "c0201 nsk" 3867.5,5562 r180 top
C61 "0201X225M6R3NT" "c0201 nsk" 3868,5476 r0 top
C62 "0201X225M6R3NT" "c0201 nsk" 3867.5,5584 r180 top
C63 "0201X225M6R3NT" "c0201 nsk" 3868,5520 r0 top
C64 "0201X225M6R3NT" "c0201 nsk" 3867.5,5628 r180 top
C65 "0201X225M6R3NT" "c0201 nsk" 3868,5541 r0 top
C66 "0201X225M6R3NT" "c0201 nsk" 3867.5,5648 r180 top
C67 "0201X225M6R3NT" "c0201 nsk" 5949,5413 r0 bottom
C68 "0201X225M6R3NT" "c0201 nsk" 5926,5433 r180 bottom
C69 "0201X225M6R3NT" "c0201 nsk" 4034,5067 r0 top
C70 "CL05A475KP5NRNC" c0402-nsk 4077.8,5257.59 r225 top
C71 "0201X225M6R3NT" "c0201 nsk" 3957,5067 r180 top
C72 "GRM155R60J226ME11D" c0402-nsk 4254.95,5107.41 r180 top
C73 "0201X225M6R3NT" "c0201 nsk" 3903,5199.5 r90 top
C74 "GRM155R60J226ME11D" c0402-nsk 4254.95,5144.69 r180 top
C75 "0201X225M6R3NT" "c0201 nsk" 5844.75,5484.75 r90 bottom
C76 "0201X225M6R3NT" "c0201 nsk" 5825.75,5484.75 r90 bottom
C77 "0201X225M6R3NT" "c0201 nsk" 5787.75,5484.75 r90 bottom
C78 "0201X225M6R3NT" "c0201 nsk" 5806.75,5484.75 r90 bottom
C79 "CL05A475KP5NRNC" c0402-nsk 3556,5470 r0 bottom
C80 "GRM155R60J226ME11D" c0402-nsk 4254.95,5186.12 r180 top
C81 "GRM155R60J226ME11D" c0402-nsk 4254.95,5228.95 r180 top
C82 "CL05A475KP5NRNC" c0402-nsk 3764,5527 r0 bottom
C83 "0201X225M6R3NT" "c0201 nsk" 5686.23,5395.81 r270 bottom
C84 "0201X225M6R3NT" "c0201 nsk" 5667.23,5395.81 r270 bottom
C85 "0201X225M6R3NT" "c0201 nsk" 5704.99,5395.64 r270 bottom
C86 "0201X225M6R3NT" "c0201 nsk" 5725.23,5395.81 r270 bottom
C87 "GRM155R60J226ME11D" c0402-nsk 4104.95,5323.63 r180 top
C88 "GRM033R61A105ME44D" "c0201 nsk" 3903,5138 r270 top
C89 "GRM155R60J226ME11D" c0402-nsk 4104.95,5366.46 r180 top
C90 "GRM033R61A104KE15D" "c0201 nsk" 5573,5418 r180 bottom
C91 "GRM033R61A104KE15D" "c0201 nsk" 5815,5172 r270 bottom
C92 "GRM033R61A104KE15D" "c0201 nsk" 5552,5491 r270 bottom
C93 "GRM033R61A104KE15D" "c0201 nsk" 5573,5397 r180 bottom
C94 "GRM033R61A104KE15D" "c0201 nsk" 5458,5494 r180 bottom
C95 "GRM033R61A104KE15D" "c0201 nsk" 3616,5336 r90 top
C96 "GRM033R61A104KE15D" "c0201 nsk" 4308,4827 r270 top
C97 "GRM033R61A104KE15D" "c0201 nsk" 4307,5413 r270 top
C98 "0201CG220J500NT" "c0201 nsk" 5347,5409.76 r90 top
C99 "0201CG220J500NT" "c0201 nsk" 5346.35,5466.15 r270 top
C100 "0201CG220J500NT" "c0201 nsk" 5353,5530.76 r90 top
C101 "0201CG220J500NT" "c0201 nsk" 5352.45,5632.82 r270 top
C102 "GRM033R61A104KE15D" "c0201 nsk" 5625,5513 r0 bottom
C103 "GRM033R61A104KE15D" "c0201 nsk" 5620,5568 r180 bottom
C104 "GRM033R61A104KE15D" "c0201 nsk" 5877,5452 r180 bottom
C105 "GRM033R61A104KE15D" "c0201 nsk" 5550,5670 r270 bottom
C106 "GRM033R61A104KE15D" "c0201 nsk" 5716,5653 r270 bottom
C107 "GRM033R61A104KE15D" "c0201 nsk" 5773,5664 r180 bottom
C108 "GRM033R61A104KE15D" "c0201 nsk" 5688,5583 r0 bottom
C109 "GRM033R61A104KE15D" "c0201 nsk" 5619.75,5589.25 r180 bottom
C110 "GRM033R61A104KE15D" "c0201 nsk" 5619.75,5611.25 r180 bottom
C111 "GRM033R61A104KE15D" "c0201 nsk" 5652,5600 r270 bottom
C112 "GRM033R61A104KE15D" "c0201 nsk" 5709,5533 r180 bottom
C113 "GRM033R61A104KE15D" "c0201 nsk" 5659,5533 r0 bottom
C114 "GRM033R61A104KE15D" "c0201 nsk" 5688,5560 r0 bottom
C115 "GRM033R61A104KE15D" "c0201 nsk" 5529,5669.5 r270 bottom
C116 "0201X225M6R3NT" "c0201 nsk" 4669,5062 r180 bottom
C117 "0201X225M6R3NT" "c0201 nsk" 4693,5190 r90 bottom
C118 "GRM033R61A104KE15D" "c0201 nsk" 4927,5110 r180 bottom
C119 "GRM033R61A104KE15D" "c0201 nsk" 5668,5191 r90 bottom
C120 "GRM033R61A104KE15D" "c0201 nsk" 4843,5403 r180 bottom
C121 "GRM033R61A104KE15D" "c0201 nsk" 4946.5,5347 r0 bottom
C122 "GRM033R61A104KE15D" "c0201 nsk" 5064,5201 r0 bottom
C123 "GRM033R61A104KE15D" "c0201 nsk" 5050,5151 r270 bottom
C124 "GRM033R61A104KE15D" "c0201 nsk" 4780,5116 r0 bottom
C125 "GRM033R61A104KE15D" "c0201 nsk" 4970,5597 r0 bottom
C126 "GRM033R61A104KE15D" "c0201 nsk" 5621.5,5252 r0 bottom
C127 "GRM033R61A104KE15D" "c0201 nsk" 5621,5275 r0 bottom
C128 "GRM033R61A104KE15D" "c0201 nsk" 5621,5336 r0 bottom
C129 "GRM033R61A104KE15D" "c0201 nsk" 5708,5192 r90 bottom
C130 "GRM033R61A104KE15D" "c0201 nsk" 4758,5467 r180 bottom
C131 "GRM033R61A104KE15D" "c0201 nsk" 4617,5074 r90 top
C132 "0201X225M6R3NT" "c0201 nsk" 5416,5196 r270 bottom
C133 "GRM033R61A104KE15D" "c0201 nsk" 5629,5168 r90 bottom
C134 "0201X225M6R3NT" "c0201 nsk" 4917,5240 r90 bottom
C135 "GRM033R61A104KE15D" "c0201 nsk" 4863,5162 r0 bottom
C136 "GRM033R61A104KE15D" "c0201 nsk" 4617,5461 r90 top
C137 "GRM033R61A104KE15D" "c0201 nsk" 4754,5208 r0 bottom
C138 "GRM033R61A104KE15D" "c0201 nsk" 5005,5186 r180 bottom
C139 "GRM033R61A104KE15D" "c0201 nsk" 4617,5506 r270 top
C140 "GRM033R61A104KE15D" "c0201 nsk" 4617,5169 r90 top
C141 "GRM033R61A104KE15D" "c0201 nsk" 4917,5435 r225 bottom
C142 "0201X225M6R3NT" "c0201 nsk" 4767,5290 r270 bottom
C143 "0201X225M6R3NT" "c0201 nsk" 4715,5586 r90 bottom
C144 "GRM033R61A104KE15D" "c0201 nsk" 4893,5596 r180 bottom
C145 "GRM033R61A104KE15D" "c0201 nsk" 5036,5502 r0 bottom
C146 "GRM033R61A104KE15D" "c0201 nsk" 4617,5124 r270 top
C147 "0201X225M6R3NT" "c0201 nsk" 4617,5216 r270 top
C148 "GRM033R61A104KE15D" "c0201 nsk" 4617,5261 r270 top
C149 "GRM033R61A104KE15D" "c0201 nsk" 4617,5308 r90 top
C150 "GRM033R61A104KE15D" "c0201 nsk" 4617,5412 r270 top
C151 "GRM033R61A104KE15D" "c0201 nsk" 4833,5200 r180 bottom
C152 "GRM033R61A104KE15D" "c0201 nsk" 4933,5007 r180 bottom
C153 "GRM033R61A104KE15D" "c0201 nsk" 5621,5296 r0 bottom
C154 "GRM033R61A104KE15D" "c0201 nsk" 5621,5316 r0 bottom
C155 "GRM033R61A104KE15D" "c0201 nsk" 5648,5191 r90 bottom
C156 "GRM033R61A104KE15D" "c0201 nsk" 4702,5351 r0 bottom
C157 "GRM033R61A104KE15D" "c0201 nsk" 4617,5028 r270 top
C158 "GRM033R61A104KE15D" "c0201 nsk" 4617,5354 r270 top
C159 "GRM033R61A104KE15D" "c0201 nsk" 4617,5554 r90 top
C160 "GRM033R61A104KE15D" "c0201 nsk" 4617,5600 r270 top
C161 "0201X225M6R3NT" "c0201 nsk" 5397,5196 r270 bottom
C162 "GRM033R61A104KE15D" "c0201 nsk" 5378,5196 r90 bottom
C163 "GRM033R61A104KE15D" "c0201 nsk" 5779,5158 r180 bottom
C164 "GRM033R61A104KE15D" "c0201 nsk" 5779,5179 r180 bottom
C165 "GRM033R61A104KE15D" "c0201 nsk" 5846,5564 r270 bottom
C166 "GRM033R61A104KE15D" "c0201 nsk" 5841,5187 r90 bottom
C167 "GRM033R61A104KE15D" "c0201 nsk" 5912,5328 r225 bottom
C168 "GRM033R61A104KE15D" "c0201 nsk" 5927,5314 r225 bottom
C169 "GRM033R61A104KE15D" "c0201 nsk" 5896,5161 r180 bottom
C170 "GRM033R61A104KE15D" "c0201 nsk" 5885,5557 r270 bottom
C171 "GRM033R61A104KE15D" "c0201 nsk" 5863,5187 r90 bottom
C172 "GRM033R61A104KE15D" "c0201 nsk" 5570,5615 r270 bottom
C173 "GRM033R61A104KE15D" "c0201 nsk" 5856,5395 r0 bottom
C174 "GRM033R61A104KE15D" "c0201 nsk" 5856,5375 r0 bottom
C175 "GRM033R61A104KE15D" "c0201 nsk" 5904,5265 r90 bottom
C176 "GRM033R61A104KE15D" "c0201 nsk" 5925,5265 r90 bottom
C177 "GRM033R61A104KE15D" "c0201 nsk" 5630,5386 r270 bottom
C178 "GRM033R61A104KE15D" "c0201 nsk" 5607.38,5385.75 r270 bottom
C179 "GRM033R61A104KE15D" "c0201 nsk" 3923.75,5900.75 r270 top
C180 "GRM033R61A104KE15D" "c0201 nsk" 3903.75,5900.75 r270 top
C181 "GRM033R61A104KE15D" "c0201 nsk" 5443.36,5622.04 r225 bottom
C182 "GRM033R61A104KE15D" "c0201 nsk" 5456.79,5608.61 r225 bottom
C183 "GRM033R61A104KE15D" "c0201 nsk" 5354.27,5758.12 r180 bottom
C184 "GRM033R61A104KE15D" "c0201 nsk" 5353.96,5778.12 r180 bottom
C185 "GRM033R61A104KE15D" "c0201 nsk" 5872,5253 r180 bottom
C186 "GRM033R61A104KE15D" "c0201 nsk" 5872,5272 r180 bottom
C187 "GRM033R61A104KE15D" "c0201 nsk" 5859,5332 r0 bottom
C188 "GRM033R61A104KE15D" "c0201 nsk" 5877,5473 r180 bottom
C189 "GRM033R61A104KE15D" "c0201 nsk" 5044,4386 r270 top
C190 "GRM033R61A104KE15D" "c0201 nsk" 5585.6,4446.1 r270 top
C191 "GRM033R61A104KE15D" "c0201 nsk" 5566.6,4446.1 r270 top
C192 "GRM033R61A104KE15D" "c0201 nsk" 5526.6,4446.1 r270 top
C193 "GRM033R61A104KE15D" "c0201 nsk" 5507.6,4446.1 r270 top
C194 "GRM033R61A104KE15D" "c0201 nsk" 5473.6,4446.1 r270 top
C195 "GRM033R61A104KE15D" "c0201 nsk" 5454.6,4446.1 r270 top
C196 "GRM033R61A104KE15D" "c0201 nsk" 5415.6,4446.1 r270 top
C197 "GRM033R61A104KE15D" "c0201 nsk" 5395.6,4446.1 r270 top
C198 "GRM033R61A104KE15D" "c0201 nsk" 5282,4446 r270 top
C199 "GRM033R61A104KE15D" "c0201 nsk" 5303,4446 r270 top
C200 "CAP_0402" c0402-nsk 6929.01,5348.72 r180 bottom
C201 "GRM033R61A104KE15D" "c0201 nsk" 5895,5233 r180 bottom
C202 "GRM033R61A104KE15D" "c0201 nsk" 5530,5605 r315 bottom
C204 "GRM033R61A104KE15D" "c0201 nsk" 7239,4115.5 r90 bottom
C208 "GRM033R61A104KE15D" "c0201 nsk" 5765,5423 r90 bottom
C209 "GRM033R61A104KE15D" "c0201 nsk" 5825,5422 r90 bottom
C210 "GRM033R61A104KE15D" "c0201 nsk" 3658,5813 r270 top
C211 "GRM033R61A104KE15D" "c0201 nsk" 5927,5492 r0 bottom
C213 "GRM033R61A104KE15D" "c0201 nsk" 5927,5513 r0 bottom
C214 "GRM033R61A104KE15D" "c0201 nsk" 5960,5525 r270 bottom
C215 "GRM033R61A104KE15D" "c0201 nsk" 5926.5,5452 r0 bottom
C216 "GRM033R61A104KE15D" "c0201 nsk" 5926.5,5472 r0 bottom
C218 "GRM033R61A104KE15D" "c0201 nsk" 3679,5813 r270 top
C219 "GRM033R61A104KE15D" "c0201 nsk" 4515.25,4148.25 r270 top
C220 "GRM033R61A104KE15D" "c0201 nsk" 4494.25,4148.25 r270 top
C221 "CAP_0402" c0402-nsk 4882.95,4411.98 r0 top
C222 "CAP_0402" c0402-nsk 4883,4380 r0 top
C223 "CAP_0402" c0402-nsk 5442.11,4342.11 r270 bottom
C224 "CAP_0402" c0402-nsk 5411.1,4342.17 r270 bottom
C225 "0201X225M6R3NT" "c0201 nsk" 4984,4736 r0 bottom
C226 "GRM033R61A104KE15D" "c0201 nsk" 4984,4755 r180 bottom
C227 "GRM033R61A104KE15D" "c0201 nsk" 5779,5137 r180 bottom
C228 "0201X225M6R3NT" "c0201 nsk" 7128,5318 r0 bottom
C229 "GRM033R61A104KE15D" "c0201 nsk" 4927.75,4761.25 r270 bottom
C230 "GRM033R61A104KE15D" "c0201 nsk" 4888,4749 r0 bottom
C231 "0201X225M6R3NT" "c0201 nsk" 5043.5,4929 r0 bottom
C232 "GRM033R61A104KE15D" "c0201 nsk" 5043,4906 r180 bottom
C233 "GRM033R61A104KE15D" "c0201 nsk" 5043,4884 r180 bottom
C234 "0201X225M6R3NT" "c0201 nsk" 7128,5341 r0 bottom
C235 "GRM033R61A104KE15D" "c0201 nsk" 4946.75,4761.25 r270 bottom
C236 "GRM033R61A104KE15D" "c0201 nsk" 7128,5292 r180 bottom
C237 "CAP_0402" c0402-nsk 6150.76,6134.49 r90 bottom
C238 "GRM033R61A104KE15D" "c0201 nsk" 6122.76,6148.49 r90 bottom
C239 "GRM033R61A104KE15D" "c0201 nsk" 6122.76,6231.49 r270 bottom
C240 "GRM033R61A104KE15D" "c0201 nsk" 6144.76,6231.49 r270 bottom
C241 "GRM033R61A104KE15D" "c0201 nsk" 6099.76,6148.49 r90 bottom
C242 "CAP_0402" c0402-nsk 6010.73,6163.85 r180 bottom
C243 "CAP_0402" c0402-nsk 6011,6198 r180 bottom
C244 "GRM033R61A104KE15D" "c0201 nsk" 3844.57,5997.22 r270 top
C245 "GRM033R61A104KE15D" "c0201 nsk" 3781.57,5997.22 r270 top
C246 "CAP_0402" c0402-nsk 7164.99,4455.28 r0 bottom
C247 "CAP_0402" c0402-nsk 3659,4955 r180 bottom
C248 "CAP_1206" C1206 5653,4033 r90 bottom
C249 "0201X225M6R3NT" "c0201 nsk" 5932,4523 r90 top
C250 "0201X225M6R3NT" "c0201 nsk" 5912,4523 r90 top
C251 "0201CG220J500NT" "c0201 nsk" 5797,4284 r90 top
C252 "0201CG220J500NT" "c0201 nsk" 5797,4340 r270 top
C253 "0201X225M6R3NT" "c0201 nsk" 5774,4484 r270 top
C254 "0201X225M6R3NT" "c0201 nsk" 5774,4531 r90 top
C255 "CAP_1206" C1206 6363,4031 r90 bottom
C256 "0201X225M6R3NT" "c0201 nsk" 6645,4517 r90 top
C257 "0201CG220J500NT" "c0201 nsk" 6527,4274 r90 top
C258 "0201X225M6R3NT" "c0201 nsk" 6625,4517 r90 top
C259 "0201CG220J500NT" "c0201 nsk" 6527,4330 r270 top
C260 "0201X225M6R3NT" "c0201 nsk" 6489,4525 r90 top
C261 "0201X225M6R3NT" "c0201 nsk" 6489,4479 r270 top
C262 "0201X225M6R3NT" "c0201 nsk" 5762.5,4199 r180 top
C263 "0201X225M6R3NT" "c0201 nsk" 5729,4439 r90 top
C264 "0201X225M6R3NT" "c0201 nsk" 6150,4265 r0 top
C265 "0201X225M6R3NT" "c0201 nsk" 5763,4246 r180 top
C266 "0201X225M6R3NT" "c0201 nsk" 6010,4185 r270 top
C267 "0201X225M6R3NT" "c0201 nsk" 5930,4185 r270 top
C268 "0201X225M6R3NT" "c0201 nsk" 6095,4524 r270 top
C269 "0201X225M6R3NT" "c0201 nsk" 6491,4198 r180 top
C270 "0201X225M6R3NT" "c0201 nsk" 6863,4256 r0 top
C271 "0201X225M6R3NT" "c0201 nsk" 6464,4416 r90 top
C272 "0201X225M6R3NT" "c0201 nsk" 6725,4184 r270 top
C273 "0201X225M6R3NT" "c0201 nsk" 6491,4240 r180 top
C274 "0201X225M6R3NT" "c0201 nsk" 6797.2,4516.38 r90 top
C275 "0201X225M6R3NT" "c0201 nsk" 6647,4185 r90 top
C276 "0201X225M6R3NT" "c0201 nsk" 6881,5438 r270 bottom
C277 "0201X225M6R3NT" "c0201 nsk" 6868,5295 r270 bottom
C280 "CAP_0402" c0402-nsk 7103,6073 r90 top
C281 "CAP_0603" C0603-NSK 6907.77,6056.2 r90 top
C282 "CAP_0603" C0603-NSK 6855.31,6056.2 r90 top
C283 "CL10A226MP8NUNE" C0603-NSK 4005,4980.46 r0 top
C284 "CL10A226MP8NUNE" C0603-NSK 4005,5031.46 r0 top
C285 "CL10A226MP8NUNE" C0603-NSK 3725,5676 r270 bottom
C286 "CL10A226MP8NUNE" C0603-NSK 3678,5676 r270 bottom
C287 "CL10A226MP8NUNE" C0603-NSK 3752,5477 r0 bottom
C288 "CL10A226MP8NUNE" C0603-NSK 3763,5329.54 r0 bottom
C289 "CL10A226MP8NUNE" C0603-NSK 3763,5279.54 r0 bottom
C290 "CL10A226MP8NUNE" C0603-NSK 3517,5777.46 r0 top
C291 "CL10A226MP8NUNE" C0603-NSK 3517,5728 r0 top
C292 "CL10A226MP8NUNE" C0603-NSK 3776,5767 r0 top
C293 "CL10A226MP8NUNE" C0603-NSK 3859,5737 r270 top
C294 "CAP_1206" C1206 4779,4119 r270 bottom
CGQ1 "IRM-H638T/TR2" SENSOR-SMD_IRM-H638T-TR2-TL 7160.88,3997.8 r90 top
CN2 "PJ-327A0-SMT" AUDIO-SMD_PJ-327A0-SMT 6193,6163 r270 top
CN3 "0533980271" CONN-SMD_2P-P1.25_053398-0X71 7148,4347 r90 top
CN4 "0533980271" CONN-SMD_2P-P1.25_053398-0X71 4122,4660 r90 top
D1 "B5819WS_C22624" SOD-323_L1.8-W1.3-LS2.5-RD 4027,4793 r90 top
D2 "SMCJ15CA_C438202" SMC_L6.9-W5.9-LS7.9-BI 3846,4068 r0 top
D3 "SS54_C22452" SMA_L4.4-W2.8-LS5.4-R-RD 3737,5160 r180 top
D4 "SS54_C22452" SMA_L4.4-W2.8-LS5.4-R-RD 3570,4668 r180 top
D5 "RClamp0524PATCT_C40960" SLP2510P8_L2.5-W1.0-P0.50-BL 5216,4282 r180 top
D6 "RClamp0524PATCT_C40960" SLP2510P8_L2.5-W1.0-P0.50-BL 5103,4282 r180 top
D7 "B5819WT_C2997265" "SOD-523_L1.2-W0.8-LS1.6-RD-1 NSK" 4866,4285 r270 top
D8 "RClamp0524PATCT_C40960" SLP2510P8_L2.5-W1.0-P0.50-BL 4990,4282 r0 top
D9 "B5819WT_C2997265" "SOD-523_L1.2-W0.8-LS1.6-RD-1 NSK" 4906,4285 r90 top
D10 "RClamp0524PATCT_C40960" SLP2510P8_L2.5-W1.0-P0.50-BL 5547.15,4382.81 r180 top
D11 "RClamp0524PATCT_C40960" SLP2510P8_L2.5-W1.0-P0.50-BL 5434.73,4383.23 r180 top
D12 "RClamp0524PATCT_C40960" SLP2510P8_L2.5-W1.0-P0.50-BL 5322,4383 r0 top
D13 "RClamp0524PATCT_C40960" SLP2510P8_L2.5-W1.0-P0.50-BL 4649.4,4086.34 r180 top
D14 "RClamp0524PATCT_C40960" SLP2510P8_L2.5-W1.0-P0.50-BL 4328,4087 r180 top
D15 "RClamp0524PATCT_C40960" SLP2510P8_L2.5-W1.0-P0.50-BL 4535,4087 r180 top
D16 "0402ESDA-05N" D0402 6950,5441 r270 bottom
D17 "0402ESDA-05N" D0402 6986,5442 r90 bottom
D18 "0402ESDA-05N" D0402 7023.24,5442.16 r270 bottom
D19 "0402ESDA-05N" D0402 7061,5442 r90 bottom
D20 "0402ESDA-05N" D0402 7097,5442 r270 bottom
D21 "0402ESDA-05N" D0402 7133,5442 r90 bottom
D22 "0402ESDA-05N" D0402 7170,5442 r270 bottom
D23 "0402ESDA-05N" D0402 7205,5442 r90 bottom
D24 "0402ESDA-05N" D0402 6777,6076 r90 top
D25 "0402ESDA-05N" D0402 6743,6076 r90 top
D26 "0402ESDA-05N" D0402 6693,6076 r90 top
D27 "0402ESDA-05N" D0402 6658,6076 r90 top
D30 "0402ESDA-05N" D0402 6812,6076 r90 top
D31 "0402ESDA-05N" D0402 6622,6076 r90 top
DC1 "DC-044A-A200" DC-IN-TH_DC-044A-20A 3843,3723.76 r90 top
FAN "FAN2510" FAN2510 5252,5852 r270 top
FEL1 "YTSA016A0252501B" SW-SMD_4P-L4.2-W3.4-P2.15-LS4.5-TL 4434,4822 r0 top
FPC1 "FPC-05FB-50PH20" FPC-SMD_50P-P0.50_FPC-05FB-50PH20 3501,4465 r90 bottom
FPC2 "FPC-05FB-30PH20" FPC-SMD_30P-P0.50_FPC-05FB-30PH20 7136,4866 r270 bottom
H1 "12251220ANG0S115001" HDR-TH_40P-P2.54-V-M-R2-C20-S2.54 4609,6293 r0 top
IMPORTED_IMAGE "IMPORTED_IMAGE" IMPORTED_IMAGE 5219,4754 r0 top
IMPORTED_IMAGE "IMPORTED_IMAGE" IMPORTED_IMAGE 4882,6160 r0 top
L1 "FXL0630-4R7-M" IND-SMD_L7.0-W6.6 3561.85,4903.18 r90 top
L2 "TFM201610ALM-1R0MTAA" ind-smd_l2.0-w1.6_1 3775,5309 r180 top
L3 "TFM201610ALM-1R0MTAA" ind-smd_l2.0-w1.6_1 3638,5693 r0 top
L4 "TFM201610ALM-1R0MTAA" ind-smd_l2.0-w1.6_1 3766,5693 r180 top
L5 "TFM201610ALM-1R0MTAA" ind-smd_l2.0-w1.6_1 3500,5520 r90 top
L6 "TFM201610ALM-1R0MTAA" ind-smd_l2.0-w1.6_1 4142.84,5103.49 r180 top
L7 "TFM201610ALM-1R0MTAA" ind-smd_l2.0-w1.6_1 4142.84,5201.49 r180 top
L8 "TFM201610ALM-1R0MTAA" ind-smd_l2.0-w1.6_1 4012.84,5319.49 r270 top
L9 "WPN252012H2R2MT" IND-SMD_L2.0-W1.6 5843,4508 r0 top
L10 "WPN252012H2R2MT" IND-SMD_L2.0-W1.6 6558,4502 r0 top
LED1 "LED_0807-RGB" RGBLED_0807 4028.63,5453.84 r0 top
LED2 "WS2812B-2020" LED-SMD_4P-L2.0-W2.0-TL_WS2812B-2020 3487.18,4152.77 r180 top
LED3 "WS2812B-2020" LED-SMD_4P-L2.0-W2.0-TL_WS2812B-2020 3487.18,4036.52 r180 top
LED4 "WS2812B-2020" LED-SMD_4P-L2.0-W2.0-TL_WS2812B-2020 3487.18,3920.26 r180 top
LED5 "WS2812B-2020" LED-SMD_4P-L2.0-W2.0-TL_WS2812B-2020 3487.18,3804 r180 top
PWR1 "YTSA016A0252501B" SW-SMD_4P-L4.2-W3.4-P2.15-LS4.5-TL 4434,5410 r0 top
Q1 "YJL2305A" SOT-23-3_L2.9-W1.3-P1.90-LS2.4-BR 4073,4226 r90 top
R1 "Res_0603" "R0603 NSK" 4066,4337 r180 top
R2 "Res_0603" "R0603 NSK" 4160,4308 r90 top
R3 "Res_0402" R0402-NSK 3908,4979 r90 top
R4 "Res_0402" R0402-NSK 3967.45,4575.76 r0 top
R5 "Res_0402" R0402-NSK 3856.85,4959.18 r0 top
R6 "Res_0402" R0402-NSK 3967.27,4614.78 r180 top
R7 "Res_0402" R0402-NSK 3784,5034 r180 top
R8 "Res_0402" R0402-NSK 3856.85,4998.18 r180 top
R9 "Res_0201" "r0201 nsk" 3595,5339 r90 top
R10 "Res_0201" "r0201 nsk" 3657,5338 r90 top
R11 "Res_0201" "r0201 nsk" 3551.77,5338.77 r90 top
R12 "Res_0201" "r0201 nsk" 3572.77,5338.77 r90 top
R13 "Res_0201" "r0201 nsk" 3514.47,5672 r270 top
R14 "Res_0201" "r0201 nsk" 3536,5672 r270 top
R17 "Res_0201" "r0201 nsk" 3990,5510 r180 top
R19 "Res_0201" "r0201 nsk" 5724.27,5788.27 r90 top
R20 "Res_0201" "r0201 nsk" 5746.27,5788.27 r90 top
R21 "Res_0201" "r0201 nsk" 4268,5001 r270 top
R22 "Res_0201" "r0201 nsk" 4308,4781 r90 top
R23 "Res_0201" "r0201 nsk" 4307.07,5369.69 r90 top
R24 "Res_0201" "r0201 nsk" 5695,5491 r0 bottom
R25 "Res_0201" "r0201 nsk" 5352.45,5580.32 r90 top
R26 "Res_0201" "r0201 nsk" 5738,5653 r270 bottom
R27 "Res_0201" "r0201 nsk" 5770,5644 r180 bottom
R28 "Res_0402" R0402-NSK 5697,5610 r180 bottom
R30 "Res_0201" "r0201 nsk" 5658,5788 r90 top
R31 "Res_0201" "r0201 nsk" 5702,5788 r90 top
R32 "Res_0201" "r0201 nsk" 5591,5788 r90 top
R33 "Res_0201" "r0201 nsk" 5636,5788 r270 top
R34 "Res_0201" "r0201 nsk" 5680,5788 r270 top
R35 "Res_0201" "r0201 nsk" 5614,5788 r270 top
R36 "Res_0201" "r0201 nsk" 5064,5162 r90 top
R37 "Res_0201" "r0201 nsk" 5098,5429 r0 top
R38 "Res_0201" "r0201 nsk" 5687,5146 r90 bottom
R39 "Res_0201" "r0201 nsk" 4894,5021 r90 bottom
R40 "Res_0201" "r0201 nsk" 4782,5062 r90 bottom
R41 "Res_0201" "r0201 nsk" 5680.15,4944.85 r0 top
R42 "Res_0201" "r0201 nsk" 6215,5310 r0 top
R43 "Res_0201" "r0201 nsk" 5828,5788 r90 top
R44 "Res_0201" "r0201 nsk" 5973,5258.47 r180 bottom
R45 "Res_0201" "r0201 nsk" 6072,5324 r0 bottom
R46 "Res_0201" "r0201 nsk" 5973,5218 r180 bottom
R47 "Res_0201" "r0201 nsk" 4866,4217 r90 top
R48 "Res_0201" "r0201 nsk" 4936,4344 r270 top
R49 "Res_0201" "r0201 nsk" 6073,5286 r180 bottom
R50 "Res_0201" "r0201 nsk" 4959,4344 r270 top
R51 "Res_0201" "r0201 nsk" 5002,4344 r270 top
R52 "Res_0201" "r0201 nsk" 4981,4344 r270 top
R53 "Res_0201" "r0201 nsk" 5023,4344 r270 top
R54 "Res_0201" "r0201 nsk" 5044,4344 r270 top
R55 "Res_0201" "r0201 nsk" 5954,5171.53 r0 bottom
R56 "Res_0201" "r0201 nsk" 5354,4021.53 r0 bottom
R57 "Res_0201" "r0201 nsk" 5354,4043.53 r0 bottom
R59 "Res_0201" "r0201 nsk" 5954,5197 r0 bottom
R60 "Res_0201" "r0201 nsk" 5361,4446 r90 top
R61 "Res_0201" "r0201 nsk" 5323,4446 r270 top
R62 "Res_0201" "r0201 nsk" 5260,4446 r270 top
R63 "Res_0201" "r0201 nsk" 6919,5451 r90 bottom
R64 "Res_0201" "r0201 nsk" 6144.76,6189.49 r270 bottom
R65 "Res_0201" "r0201 nsk" 6122.76,6189.49 r90 bottom
R66 "Res_0201" "r0201 nsk" 6099.76,6190.49 r90 bottom
R67 "Res_0201" "r0201 nsk" 5996,6138 r180 bottom
R68 "Res_0201" "r0201 nsk" 5996,6225 r180 bottom
R69 "Res_0201" "r0201 nsk" 3912.28,5841.7 r0 top
R70 "Res_0201" "r0201 nsk" 3912,5817 r0 top
R72 "Res_0201" "r0201 nsk" 3812.57,5986.22 r180 top
R73 "Res_0201" "r0201 nsk" 5920,6135 r0 bottom
R74 "Res_0201" "r0201 nsk" 5977,5980 r90 bottom
R75 "Res_0201" "r0201 nsk" 5569,6029 r90 bottom
R76 "Res_0201" "r0201 nsk" 7057,4198 r270 bottom
R77 "Res_0201" "r0201 nsk" 7047.19,4265.26 r90 top
R78 "Res_0201" "r0201 nsk" 7067.26,4265.34 r90 top
R79 "Res_0201" "r0201 nsk" 5608,3682 r270 top
R80 "Res_0201" "r0201 nsk" 5631,3682 r90 top
R82 "Res_0201" "r0201 nsk" 6047,4523 r270 top
R83 "Res_0201" "r0201 nsk" 6150,4320 r180 top
R85 "Res_0201" "r0201 nsk" 5763,4223 r0 top
R86 "Res_0201" "r0201 nsk" 6023.47,4523 r270 top
R88 "Res_0201" "r0201 nsk" 5762,4449 r0 top
R89 "Res_0201" "r0201 nsk" 5999,4523 r90 top
R90 "Res_0201" "r0201 nsk" 6150,4288 r180 top
R91 "Res_0201" "r0201 nsk" 6072,4523 r90 top
R92 "Res_0201" "r0201 nsk" 5762,4427 r180 top
R93 "Res_0201" "r0201 nsk" 5954,4523 r270 top
R94 "Res_0201" "r0201 nsk" 5631,3725 r270 top
R95 "Res_0201" "r0201 nsk" 5976,4523 r270 top
R96 "Res_0201" "r0201 nsk" 5608,3725 r270 top
R97 "Res_0201" "r0201 nsk" 6338.37,3678.12 r270 top
R98 "Res_0201" "r0201 nsk" 6362.37,3678.12 r90 top
R100 "Res_0201" "r0201 nsk" 6754,4517 r270 top
R101 "Res_0201" "r0201 nsk" 6863,4314 r180 top
R103 "Res_0201" "r0201 nsk" 6491,4219 r0 top
R104 "Res_0201" "r0201 nsk" 6732,4517 r270 top
R106 "Res_0201" "r0201 nsk" 6494,4426 r0 top
R107 "Res_0201" "r0201 nsk" 6709,4517 r90 top
R108 "Res_0201" "r0201 nsk" 6863,4280.53 r180 top
R109 "Res_0201" "r0201 nsk" 6776,4517 r90 top
R110 "Res_0201" "r0201 nsk" 6494,4405 r180 top
R111 "Res_0201" "r0201 nsk" 6666,4517 r270 top
R112 "Res_0201" "r0201 nsk" 6362.37,3719.12 r270 top
R113 "Res_0201" "r0201 nsk" 6687,4517 r270 top
R114 "Res_0201" "r0201 nsk" 6338.37,3719.12 r270 top
R115 "Res_0201" "r0201 nsk" 6787,5282 r90 bottom
R116 "Res_0201" "r0201 nsk" 6765,5282 r270 bottom
R117 "Res_0201" "r0201 nsk" 6962.77,5975.66 r0 top
R118 "Res_0201" "r0201 nsk" 7067.77,5975.2 r0 top
R119 "Res_0201" "r0201 nsk" 6775,5483 r180 bottom
R120 "Res_0201" "r0201 nsk" 6973.23,6155.23 r270 top
R121 "Res_0201" "r0201 nsk" 6994,6155 r90 top
R122 "Res_0201" "r0201 nsk" 6074.76,6190.49 r90 bottom
R123 "Res_0201" "r0201 nsk" 5920,5793 r270 top
R124 "Res_0201" "r0201 nsk" 7052.62,4125.46 r90 top
R125 "Res_0201" "r0201 nsk" 7073.62,4125.46 r90 top
R126 "Res_0402" R0402-NSK 6841,5268 r90 bottom
R127 "Res_0201" "r0201 nsk" 6058,5562 r180 bottom
R128 "Res_0201" "r0201 nsk" 6058,5539 r180 bottom
R129 "Res_0201" "r0201 nsk" 6594,6085 r90 top
R130 "Res_0201" "r0201 nsk" 6782,6020 r180 top
RESET1 "YTSA016A0252501B" SW-SMD_4P-L4.2-W3.4-P2.15-LS4.5-TL 4434,5116 r0 top
RF1 "BWIPX-1-001E" IPEX-SMD_BWIPX-1-001E 3708,5986 r180 top
RJ1 "HR911130A" RJ45-TH_HR911130A 5993,3791.76 r180 top
RJ2 "HR911130A" RJ45-TH_HR911130A 6712,3791 r180 top
SIM1 "1040310811" SIM-SMD_8P-1040310811 7028,5769 r270 bottom
TFT1 "1.14 IPS DISPLAY ST7789V" TFT_1.14寸_0.7MM-13P 6923,5232 r270 top
U1 "RVT1H101M0607" CAP-SMD_BD6.3-L6.6-W6.6-LS7.6-RD 3567.64,4414.49 r90 top
U2 "RVT1H101M0607" CAP-SMD_BD6.3-L6.6-W6.6-LS7.6-RD 3860.52,4414.64 r90 top
U3 "TPS54531DDAR" SOIC-8_L5.0-W4.0-P1.27-LS6.0-BL-EP2.0 3845,4780 r0 top
U4 "AXP717B" QFN-52_L6.0-W6.0-P0.40-BL-EP3.4-1 3689.11,5500.48 r0 top
U5 "AXP323" QFN-20_L3.0-W3.0-P0.40-BL-EP1.5 3987.84,5153.49 r180 top
U8 "EMMC BGA153" FBGA-153_L13.0-W11.5 4900,4745 r270 top
U9 "XR829MQ" LGA-44_L12.0-W12.0-P0.90 4196,5843 r0 top
U11 "TJA1051T_C7432801" SOP-8_L4.9-W3.9-P1.27-LS6.0-BL 7164,4287 r0 bottom
U12 "RTL8211F-CG" WQFN-40_L5.0-W5.0-P0.4-BL-EP 5970,4343 r0 top
U13 "RTL8211F-CG" WQFN-40_L5.0-W5.0-P0.4-BL-EP 6684.91,4337.51 r0 top
U14 "T527" T527-BGA664 5766.98,5355.47 r270 top
U15 "DP_TH_SIDE_VERTICAL" DP_TH_SIDE_VERTICAL 5439,3797 r180 top
U16 "SY6280AAC_C55136" SOT-23-5_L3.0-W1.7-P0.95-LS2.8-BL 6803.51,5385.73 r180 bottom
U17 "SY6280AAC_C55136" SOT-23-5_L3.0-W1.7-P0.95-LS2.8-BL 7014.46,6055.02 r270 top
U18 "W25N01GVZEIG_C88868" WSON-8_L8.0-W6.10-P1.27-BL-EP 5770,5994 r270 bottom
UD1 "LPDDR4_FBGA200" BGA200P65_80B1000_1500H90 4836.54,5314.87 r180 top
USB1 "HDMI-001C_C2836126" HDMI-SMD_HDMI-001C 5042.58,3905.2 r270 top
USB2 "USB-303WSD-BRY" USB-A-TH_XUNPU_USB-303WSD-BRY 4491,3798 r0 top
USB3 "TYPEC-304-BCP16" USB-C-SMD_TYPEC-304-BCP16-1 6720,6259 r180 top
X1 "TAXM24M4ZDBCCT2T" crystal-smd_4p-l2.0-w1.6-bl-nsk 5298,5438.46 r270 top
X2 "Q13FC1350000400" "osc-smd_l3.2-w1.5 nsk" 5298.45,5582.32 r90 top
X3 "7D025000Q01" crystal-smd_4p-l2.0-w1.6-bl-nsk 5749,4314 r270 top
X4 "7D025000Q01" crystal-smd_4p-l2.0-w1.6-bl-nsk 6478,4302 r270 top

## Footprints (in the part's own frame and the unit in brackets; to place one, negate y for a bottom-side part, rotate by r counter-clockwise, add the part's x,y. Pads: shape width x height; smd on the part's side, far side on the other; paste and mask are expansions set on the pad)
AUDIO-SMD_PJ-327A0-SMT [mm]
  rect 1.8x3 smd: 2(3.15,-4.028) 3(-3.75,-4.028) 4(-4.75,4.028) 5(-1.15,4.028) 6(4.75,4.028)
  Board Outline Layer lines w0.254: -6.24,-2.54 -6.24,2.56 ; -6.24,-2.54 -8.34,-2.54 -6.24,-2.54 ; -6.24,-2.54 -6.24,2.56 ; -6.24,2.56 -6.4,2.56 ; -6.24,2.56 -6.4,2.56 ; -6.4,2.56 -8.44,2.56 -6.4,2.56
  Multi-Layer board cut-out: -3.35,0.5 -3.622,0.424 -3.82,0.223 -3.892,-0.05 -3.82,-0.323 -3.622,-0.524 -3.35,-0.6 -3.35,-0.6 -3.078,-0.524 -2.88,-0.323 -2.807,-0.05 -2.88,0.223 -3.078,0.424 -3.35,0.5
  Multi-Layer board cut-out: 2.65,0.5 2.378,0.424 2.18,0.223 2.108,-0.05 2.18,-0.323 2.378,-0.524 2.65,-0.6 2.65,-0.6 2.922,-0.524 3.12,-0.323 3.193,-0.05 3.12,0.223 2.922,0.424 2.65,0.5
  Multi-Layer keep-out circle w0.254: c-3.35,-0.05 r0.55
  Multi-Layer keep-out circle w0.254: c2.65,-0.05 r0.55
  silkscreen extent -8.43,-3.23 5.6,3.17
BGA200P65_80B1000_1500H90 [mm]
  round 0.27 smd: A1(-4.4,6.825) A2(-3.6,6.825) A3(-2.8,6.825) A4(-2,6.825) A5(-1.2,6.825) A8(1.2,6.825) A9(2,6.825) A10(2.8,6.825) A11(3.6,6.825) A12(4.4,6.825) AA1(-4.4,-6.175) AA2(-3.6,-6.175) AA3(-2.8,-6.175) AA4(-2,-6.175) AA5(-1.2,-6.175) AA8(1.2,-6.175) AA9(2,-6.175) AA10(2.8,-6.175) AA11(3.6,-6.175) AA12(4.4,-6.175) AB1(-4.4,-6.825) AB2(-3.6,-6.825) AB3(-2.8,-6.825) AB4(-2,-6.825) AB5(-1.2,-6.825) AB8(1.2,-6.825) AB9(2,-6.825) AB10(2.8,-6.825) AB11(3.6,-6.825) AB12(4.4,-6.825) B1(-4.4,6.175) B2(-3.6,6.175) B3(-2.8,6.175) B4(-2,6.175) B5(-1.2,6.175) B8(1.2,6.175) B9(2,6.175) B10(2.8,6.175) B11(3.6,6.175) B12(4.4,6.175) C1(-4.4,5.525) C2(-3.6,5.525) C3(-2.8,5.525) C4(-2,5.525) C5(-1.2,5.525) C8(1.2,5.525) C9(2,5.525) C10(2.8,5.525) C11(3.6,5.525) C12(4.4,5.525) D1(-4.4,4.875) D2(-3.6,4.875) D3(-2.8,4.875) D4(-2,4.875) D5(-1.2,4.875) D8(1.2,4.875) D9(2,4.875) D10(2.8,4.875) D11(3.6,4.875) D12(4.4,4.875) E1(-4.4,4.225) E2(-3.6,4.225) E3(-2.8,4.225) E4(-2,4.225) E5(-1.2,4.225) E8(1.2,4.225) E9(2,4.225) E10(2.8,4.225) E11(3.6,4.225) E12(4.4,4.225) F1(-4.4,3.575) F2(-3.6,3.575) F3(-2.8,3.575) F4(-2,3.575) F5(-1.2,3.575) F8(1.2,3.575) F9(2,3.575) F10(2.8,3.575) F11(3.6,3.575) F12(4.4,3.575) G1(-4.4,2.925) G2(-3.6,2.925) G3(-2.8,2.925) G4(-2,2.925) G5(-1.2,2.925) G8(1.2,2.925) G9(2,2.925) G10(2.8,2.925) G11(3.6,2.925) G12(4.4,2.925) H1(-4.4,2.275) H2(-3.6,2.275) H3(-2.8,2.275) H4(-2,2.275) H5(-1.2,2.275) H8(1.2,2.275) H9(2,2.275) H10(2.8,2.275) H11(3.6,2.275) H12(4.4,2.275) J1(-4.4,1.625) J2(-3.6,1.625) J3(-2.8,1.625) J4(-2,1.625) J5(-1.2,1.625) J8(1.2,1.625) J9(2,1.625) J10(2.8,1.625) J11(3.6,1.625) J12(4.4,1.625) K1(-4.4,0.975) K2(-3.6,0.975) K3(-2.8,0.975) K4(-2,0.975) K5(-1.2,0.975) K8(1.2,0.975) K9(2,0.975) K10(2.8,0.975) K11(3.6,0.975) K12(4.4,0.975) N1(-4.4,-0.975) N2(-3.6,-0.975) N3(-2.8,-0.975) N4(-2,-0.975) N5(-1.2,-0.975) N8(1.2,-0.975) N9(2,-0.975) N10(2.8,-0.975) N11(3.6,-0.975) N12(4.4,-0.975) P1(-4.4,-1.625) P2(-3.6,-1.625) P3(-2.8,-1.625) P4(-2,-1.625) P5(-1.2,-1.625) P8(1.2,-1.625) P9(2,-1.625) P10(2.8,-1.625) P11(3.6,-1.625) P12(4.4,-1.625) R1(-4.4,-2.275) R2(-3.6,-2.275) R3(-2.8,-2.275) R4(-2,-2.275) R5(-1.2,-2.275) R8(1.2,-2.275) R9(2,-2.275) R10(2.8,-2.275) R11(3.6,-2.275) R12(4.4,-2.275) T1(-4.4,-2.925) T2(-3.6,-2.925) T3(-2.8,-2.925) T4(-2,-2.925) T5(-1.2,-2.925) T8(1.2,-2.925) T9(2,-2.925) T10(2.8,-2.925) T11(3.6,-2.925) T12(4.4,-2.925) U1(-4.4,-3.575) U2(-3.6,-3.575) U3(-2.8,-3.575) U4(-2,-3.575) U5(-1.2,-3.575) U8(1.2,-3.575) U9(2,-3.575) U10(2.8,-3.575) U11(3.6,-3.575) U12(4.4,-3.575) V1(-4.4,-4.225) V2(-3.6,-4.225) V3(-2.8,-4.225) V4(-2,-4.225) V5(-1.2,-4.225) V8(1.2,-4.225) V9(2,-4.225) V10(2.8,-4.225) V11(3.6,-4.225) V12(4.4,-4.225) W1(-4.4,-4.875) W2(-3.6,-4.875) W3(-2.8,-4.875) W4(-2,-4.875) W5(-1.2,-4.875) W8(1.2,-4.875) W9(2,-4.875) W10(2.8,-4.875) W11(3.6,-4.875) W12(4.4,-4.875) Y1(-4.4,-5.525) Y2(-3.6,-5.525) Y3(-2.8,-5.525) Y4(-2,-5.525) Y5(-1.2,-5.525) Y8(1.2,-5.525) Y9(2,-5.525) Y10(2.8,-5.525) Y11(3.6,-5.525) Y12(4.4,-5.525)
  silkscreen extent -5.75,-7.55 5.05,7.55
"c0201 nsk" [mil]
  rect 14.51x12.76 smd: 1(-11.5,0) 2(11,0)
c0402-nsk [mil]
  rect 22x22 smd: 1(-19.99,0) 2(20.01,0)
  silkscreen extent 0,-5 0,6
C0603-NSK [mm]
  rect 0.85x0.85 smd: 1(-0.75,0) 2(0.75,0)
  silkscreen extent 0,-0.21 0,0.21
"C0805 NSK" [mm]
  rect 1.3x1.35 smd: 1(-1.03,0) 2(1.03,0)
  silkscreen extent 0,-0.44 0,0.44
C1206 [mm]
  rect 1.485x1.728 smd: 1(-1.593,0) 2(1.593,0)
  silkscreen extent -2.56,-1.09 2.56,1.09
CAP-SMD_BD6.3-L6.6-W6.6-LS7.6-RD [mm]
  rect 3.5x1.2 smd: 1(-2.67,0) 2(2.67,0)
  silkscreen extent -3.38,-3.38 3.38,3.38
CONN-SMD_2P-P1.25_053398-0X71 [mm]
  rect 0.8x1.6 smd: 1(-0.63,1.45) 2(0.63,1.45)
  rect 2x3 smd: 3(3.23,-1.45) 4(-3.23,-1.45)
  silkscreen extent -3.68,-2.6 3.68,1.21
crystal-smd_4p-l2.0-w1.6-bl-nsk [mil]
  rect 33.3x21.5 smd: 1(-30,-20) 2(30,-20) 3(30,20) 4(-30,20)
D0402 [mil]
  rect 19.89x21.68 smd: 1(-16.4,0) 2(16.4,0)
  silkscreen extent -37,-9 -31,9
DC-IN-TH_DC-044A-20A [mm]
  oval 3x1.6 hole 1 slot 2.2 at 0 deg: 1(3.625,-4.5) 2(3.625,4.001) 3(3.625,-1.3) 4(-3.625,-4.9) 5(-3.625,4.9)
  Multi-Layer board cut-out: -2.6,-2.3 -2.079,-2.156 -1.699,-1.772 -1.56,-1.25 -1.699,-0.728 -2.079,-0.344 -2.6,-0.2 -2.6,-0.2 -3.121,-0.344 -3.501,-0.728 -3.64,-1.25 -3.501,-1.772 -3.121,-2.156 -2.6,-2.3
  Multi-Layer keep-out circle w0.254: c-2.6,-1.25 r1.05
  silkscreen extent -6.7,-5.1 4.95,5
DP_TH_SIDE_VERTICAL [mil]
  round 35 hole 25: 1(-30.5,34.6) 2(28.5,60.2) 3(-30.5,-16.6) 4(28.5,9) 5(-30.5,-67.7) 6(28.5,-42.2) 7(-30.5,-118.9) 8(28.5,-93.3) 9(-30.5,-170.1) 10(28.5,-144.5) 11(-30.5,-221.3) 12(28.5,-195.7) 13(-30.5,-272.5) 14(28.5,-246.9) 15(-30.5,-323.7) 16(28.5,-298.1) 17(-30.5,-374.8) 18(28.5,-349.2) 19(-30.5,-426) 20(28.5,-400.4)
  oval 47.2x94.5 hole 39.37 slot 78.74 at 90 deg: 21(98.6,100.8) 22(98.6,-354) 23(-100.6,-436.6) 24(-100.6,27.9)
  Multi-Layer board cut-out: 32,-446 34.97,-459.02 43.3,-469.45 55.32,-475.25 68.68,-475.25 80.7,-469.45 89.03,-459.02 92,-446 92,-446 89.03,-432.98 80.7,-422.55 68.68,-416.75 55.32,-416.75 43.3,-422.55 34.97,-432.98 32,-446
  Multi-Layer board cut-out: -94,105.5 -91.03,92.48 -82.7,82.05 -70.68,76.25 -57.32,76.25 -45.3,82.05 -36.97,92.48 -34,105.5 -34,105.5 -36.97,118.52 -45.3,128.95 -57.32,134.75 -70.68,134.75 -82.7,128.95 -91.03,118.52 -94,105.5
  Multi-Layer keep-out circle w10: c62,-446 r30
  Multi-Layer keep-out circle w10: c-64,105.5 r30
  silkscreen extent -119,-513 117,511
FAN2510 [mm]
  round 3.5 hole 2.7: 1(28.321,23.114) 2(-2.54,2.921)
FBGA-153_L13.0-W11.5 [mm]
  oval 0.2x0.305 smd: A1(-3.25,3.25) A2(-2.75,3.25) A3(-2.25,3.25) A4(-1.75,3.25) A5(-1.25,3.25) A6(-0.75,3.25) A7(-0.25,3.25) A8(0.25,3.25) A9(0.75,3.25) A10(1.25,3.25) A11(1.75,3.25) A12(2.25,3.25) A13(2.75,3.25) A14(3.25,3.25) P1(-3.25,-3.25) P2(-2.75,-3.25) P3(-2.25,-3.25) P4(-1.75,-3.25) P5(-1.25,-3.25) P6(-0.75,-3.25) P7(-0.25,-3.25) P8(0.25,-3.25) P9(0.75,-3.25) P10(1.25,-3.25) P11(1.75,-3.25) P12(2.25,-3.25) P13(2.75,-3.25) P14(3.25,-3.25)
  oval 0.305x0.2 smd: B1(-3.25,2.75) B14(3.25,2.75) C1(-3.25,2.25) C14(3.25,2.25) D1(-3.25,1.75) D14(3.25,1.75) E1(-3.25,1.25) E14(3.25,1.25) F1(-3.25,0.75) F14(3.25,0.75) G1(-3.25,0.25) G14(3.25,0.25) H1(-3.25,-0.25) H14(3.25,-0.25) J1(-3.25,-0.75) J14(3.25,-0.75) K1(-3.25,-1.25) K14(3.25,-1.25) L1(-3.25,-1.75) L14(3.25,-1.75) M1(-3.25,-2.25) M14(3.25,-2.25) N1(-3.25,-2.75) N14(3.25,-2.75)
  round 0.25 smd: B2(-2.75,2.75) B3(-2.25,2.75) B4(-1.75,2.75) B5(-1.25,2.75) B6(-0.75,2.75) B7(-0.25,2.75) B8(0.25,2.75) B9(0.75,2.75) B10(1.25,2.75) B11(1.75,2.75) B12(2.25,2.75) B13(2.75,2.75) C2(-2.75,2.25) C3(-2.25,2.25) C4(-1.75,2.25) C5(-1.25,2.25) C6(-0.75,2.25) C7(-0.25,2.25) C8(0.25,2.25) C9(0.75,2.25) C10(1.25,2.25) C11(1.75,2.25) C12(2.25,2.25) C13(2.75,2.25) D2(-2.75,1.75) D3(-2.25,1.75) D4(-1.75,1.75) D12(2.25,1.75) D13(2.75,1.75) E2(-2.75,1.25) E3(-2.25,1.25) E5(-1.25,1.25) E6(-0.75,1.25) E7(-0.25,1.25) E8(0.25,1.25) E9(0.75,1.25) E10(1.25,1.25) E12(2.25,1.25) E13(2.75,1.25) F2(-2.75,0.75) F3(-2.25,0.75) F5(-1.25,0.75) F10(1.25,0.75) F12(2.25,0.75) F13(2.75,0.75) G2(-2.75,0.25) G3(-2.25,0.25) G5(-1.25,0.25) G10(1.25,0.25) G12(2.25,0.25) G13(2.75,0.25) H2(-2.75,-0.25) H3(-2.25,-0.25) H5(-1.25,-0.25) H10(1.25,-0.25) H12(2.25,-0.25) H13(2.75,-0.25) J2(-2.75,-0.75) J3(-2.25,-0.75) J5(-1.25,-0.75) J10(1.25,-0.75) J12(2.25,-0.75) J13(2.75,-0.75) K2(-2.75,-1.25) K3(-2.25,-1.25) K5(-1.25,-1.25) K6(-0.75,-1.25) K7(-0.25,-1.25) K8(0.25,-1.25) K9(0.75,-1.25) K10(1.25,-1.25) K12(2.25,-1.25) K13(2.75,-1.25) L2(-2.75,-1.75) L3(-2.25,-1.75) L12(2.25,-1.75) L13(2.75,-1.75) M2(-2.75,-2.25) M3(-2.25,-2.25) M4(-1.75,-2.25) M5(-1.25,-2.25) M6(-0.75,-2.25) M7(-0.25,-2.25) M8(0.25,-2.25) M9(0.75,-2.25) M10(1.25,-2.25) M11(1.75,-2.25) M12(2.25,-2.25) M13(2.75,-2.25) N2(-2.75,-2.75) N3(-2.25,-2.75) N4(-1.75,-2.75) N5(-1.25,-2.75) N6(-0.75,-2.75) N7(-0.25,-2.75) N8(0.25,-2.75) N9(0.75,-2.75) N10(1.25,-2.75) N11(1.75,-2.75) N12(2.25,-2.75) N13(2.75,-2.75)
  silkscreen extent -5.84,-6.61 5.84,6.6
FPC-SMD_30P-P0.50_FPC-05FB-30PH20 [mm]
  rect 0.3x1.2 smd: 1(7.25,1.625) 2(6.75,1.625) 3(6.25,1.625) 4(5.75,1.625) 5(5.25,1.625) 6(4.75,1.625) 7(4.25,1.625) 8(3.75,1.625) 9(3.25,1.625) 10(2.75,1.625) 11(2.25,1.625) 12(1.75,1.625) 13(1.25,1.625) 14(0.75,1.625) 15(0.25,1.625) 16(-0.25,1.625) 17(-0.75,1.625) 18(-1.25,1.625) 19(-1.75,1.625) 20(-2.25,1.625) 21(-2.75,1.625) 22(-3.25,1.625) 23(-3.75,1.625) 24(-4.25,1.625) 25(-4.75,1.625) 26(-5.25,1.625) 27(-5.75,1.625) 28(-6.25,1.625) 29(-6.75,1.625) 30(-7.25,1.625)
  rect 2x1.8 smd: 31(-8.8,-1.625) 32(8.8,-1.625)
  silkscreen extent -9.25,-3.55 9.25,2.13
FPC-SMD_50P-P0.50_FPC-05FB-50PH20 [mm]
  rect 0.3x1.2 smd: 1(12.25,1.625) 2(11.75,1.625) 3(11.25,1.625) 4(10.75,1.625) 5(10.25,1.625) 6(9.75,1.625) 7(9.25,1.625) 8(8.75,1.625) 9(8.25,1.625) 10(7.75,1.625) 11(7.25,1.625) 12(6.75,1.625) 13(6.25,1.625) 14(5.75,1.625) 15(5.25,1.625) 16(4.75,1.625) 17(4.25,1.625) 18(3.75,1.625) 19(3.25,1.625) 20(2.75,1.625) 21(2.25,1.625) 22(1.75,1.625) 23(1.25,1.625) 24(0.75,1.625) 25(0.25,1.625) 26(-0.25,1.625) 27(-0.75,1.625) 28(-1.25,1.625) 29(-1.75,1.625) 30(-2.25,1.625) 31(-2.75,1.625) 32(-3.25,1.625) 33(-3.75,1.625) 34(-4.25,1.625) 35(-4.75,1.625) 36(-5.25,1.625) 37(-5.75,1.625) 38(-6.25,1.625) 39(-6.75,1.625) 40(-7.25,1.625) 41(-7.75,1.625) 42(-8.25,1.625) 43(-8.75,1.625) 44(-9.25,1.625) 45(-9.75,1.625) 46(-10.25,1.625) 47(-10.75,1.625) 48(-11.25,1.625) 49(-11.75,1.625) 50(-12.25,1.625)
  rect 2x1.8 smd: 51(-13.8,-1.625) 52(13.8,-1.625)
  silkscreen extent -14.25,-3.88 14.25,2.13
HDMI-SMD_HDMI-001C [mm]
  round 0.8 hole 0.55: 1(5.3,0.5) 2(4.731,-0.5) 3(4.145,0.5) 4(3.575,-0.5) 5(2.99,0.5) 6(2.419,-0.5) 7(1.835,0.5) 8(1.263,-0.5) 9(0.68,0.5) 10(0.107,-0.5) 11(-0.475,0.5) 12(-1.049,-0.5) 13(-1.63,0.5) 14(-2.205,-0.5) 15(-2.785,0.5) 16(-3.361,-0.5) 17(-3.94,0.5) 18(-4.517,-0.5) 19(-5.095,0.5)
  oval 3.2x1.4 hole 0.9 slot 2.7 at 0 deg: 20(-6.05,3.25) 20(-2.95,-3.25) 20(3.45,3.25) 20(6.05,-3.25)
  Multi-Layer board cut-out: 7.2,2.516 6.759,2.415 6.406,2.133 6.209,1.726 6.209,1.274 6.406,0.867 6.759,0.585 7.2,0.484 7.2,0.484 7.708,0.62 8.08,0.992 8.216,1.5 8.08,2.008 7.708,2.38 7.2,2.516
  Multi-Layer board cut-out: -6.05,-0.984 -6.491,-1.085 -6.844,-1.367 -7.04,-1.774 -7.04,-2.226 -6.844,-2.634 -6.491,-2.916 -6.05,-3.016 -6.05,-3.016 -5.542,-2.88 -5.17,-2.508 -5.034,-2 -5.17,-1.492 -5.542,-1.12 -6.05,-0.984
  Multi-Layer keep-out circle w0.254: c7.2,1.5 r1.016
  Multi-Layer keep-out circle w0.254: c-6.05,-2 r1.016
  silkscreen extent -7.4,-3.85 15.7,3.25
HDR-TH_40P-P2.54-V-M-R2-C20-S2.54 [mm]
  rect 1.575x1.8 hole 1.1: 1(-24.13,-1.27)
  round 1.8 hole 1.1: 2(-24.13,1.27) 3(-21.59,-1.27) 4(-21.59,1.27) 5(-19.05,-1.27) 6(-19.05,1.27) 7(-16.51,-1.27) 8(-16.51,1.27) 9(-13.97,-1.27) 10(-13.97,1.27) 11(-11.43,-1.27) 12(-11.43,1.27) 13(-8.89,-1.27) 14(-8.89,1.27) 15(-6.35,-1.27) 16(-6.35,1.27) 17(-3.81,-1.27) 18(-3.81,1.27) 19(-1.27,-1.27) 20(-1.27,1.27) 21(1.27,-1.27) 22(1.27,1.27) 23(3.81,-1.27) 24(3.81,1.27) 25(6.35,-1.27) 26(6.35,1.27) 27(8.89,-1.27) 28(8.89,1.27) 29(11.43,-1.27) 30(11.43,1.27) 31(13.97,-1.27) 32(13.97,1.27) 33(16.51,-1.27) 34(16.51,1.27) 35(19.05,-1.27) 36(19.05,1.27) 37(21.59,-1.27) 38(21.59,1.27) 39(24.13,-1.27) 40(24.13,1.27)
  silkscreen extent -25.4,-2.54 25.4,2.54
IMPORTED_IMAGE [mil]
IND-SMD_L2.0-W1.6 [mm]
  rect 1x1.72 smd: 1(0.828,0) 2(-0.828,0)
  silkscreen extent -1.14,-1.02 1.14,1.02
ind-smd_l2.0-w1.6_1 [mil]
  rect 46x77 smd: 1(35,0) 2(-35,0)
  silkscreen extent -45,-45 45,45
IND-SMD_L7.0-W6.6 [mm]
  rect 2.4x3.2 smd: 1(-3,0) 2(3,0)
  silkscreen extent -3.5,-3.3 3.5,3.3
IPEX-SMD_BWIPX-1-001E [mm]
  rect 1.05x1 smd: 1(-0.763,0)
  rect 2.2x1.05 smd: 2(0.763,-1.475) 3(0.763,1.475)
  silkscreen extent -0.64,-1.27 2.16,1.27
LED-SMD_4P-L2.0-W2.0-TL_WS2812B-2020 [mm]
  rect 0.9x0.7 smd: 1(-0.915,0.55) 2(-0.915,-0.55) 3(0.915,-0.55) 4(0.915,0.55)
  silkscreen extent -1.3,-1.1 1,1.15
LGA-44_L12.0-W12.0-P0.90 [mm]
  rect 1.177x0.6 smd: 1(-5.844,4.5) 2(-5.844,3.6) 3(-5.844,2.7) 4(-5.844,1.8) 5(-5.844,0.9) 6(-5.844,0) 7(-5.844,-0.9) 8(-5.844,-1.8) 9(-5.844,-2.7) 10(-5.844,-3.6) 11(-5.844,-4.5) 23(5.844,-4.5) 24(5.844,-3.6) 25(5.844,-2.7) 26(5.844,-1.8) 27(5.844,-0.9) 28(5.844,0) 29(5.844,0.9) 30(5.844,1.8) 31(5.844,2.7) 32(5.844,3.6) 33(5.844,4.5)
  rect 0.6x1.177 smd: 12(-4.5,-5.844) 13(-3.6,-5.844) 14(-2.7,-5.844) 15(-1.8,-5.844) 16(-0.9,-5.844) 17(0,-5.844) 18(0.9,-5.844) 19(1.8,-5.844) 20(2.7,-5.844) 21(3.6,-5.844) 22(4.5,-5.844) 34(4.5,5.844) 35(3.6,5.844) 36(2.7,5.844) 37(1.8,5.844) 38(0.9,5.844) 39(0,5.844) 40(-0.9,5.844) 41(-1.8,5.844) 42(-2.7,5.844) 43(-3.6,5.844) 44(-4.5,5.844)
  silkscreen extent -7.47,-6.08 6.08,6.08
"osc-smd_l3.2-w1.5 nsk" [mm]
  rect 1.05x1.7 smd: 1(-1.275,0) 2(1.275,0)
QFN-20_L3.0-W3.0-P0.40-BL-EP1.5 [mm]
  rect 0.2x0.665 smd: 1(-0.8,-1.407) 2(-0.4,-1.407) 3(0,-1.407) 4(0.4,-1.407) 5(0.8,-1.407) 11(0.8,1.407) 12(0.4,1.407) 13(0,1.407) 14(-0.4,1.407) 15(-0.8,1.407)
  rect 0.665x0.2 smd: 6(1.407,-0.8) 7(1.407,-0.4) 8(1.407,0) 9(1.407,0.4) 10(1.407,0.8) 16(-1.407,0.8) 17(-1.407,0.4) 18(-1.407,0) 19(-1.407,-0.4) 20(-1.407,-0.8)
  rect 1.5x1.5 smd: 21(0,0)
  silkscreen extent -1.58,-2.01 1.58,1.58
QFN-52_L6.0-W6.0-P0.40-BL-EP3.4-1 [mm]
  oval 0.12x0.351 smd: 1(-2.4,-2.918) 13(2.4,-2.918) 27(2.4,2.917) 39(-2.4,2.917)
  rect 0.2x0.585 smd: 2(-2,-2.918) 3(-1.6,-2.918) 4(-1.2,-2.918) 5(-0.8,-2.918) 6(-0.4,-2.918) 7(0,-2.918) 8(0.4,-2.918) 9(0.8,-2.918) 10(1.2,-2.918) 11(1.6,-2.918) 12(2,-2.918) 28(2,2.917) 29(1.6,2.917) 30(1.2,2.917) 31(0.8,2.917) 32(0.4,2.917) 33(0,2.917) 34(-0.4,2.917) 35(-0.8,2.917) 36(-1.2,2.917) 37(-1.6,2.917) 38(-2,2.917)
  oval 0.351x0.12 smd: 14(2.917,-2.4) 26(2.918,2.4) 40(-2.917,2.4) 52(-2.917,-2.4)
  rect 0.585x0.2 smd: 15(2.917,-2) 16(2.917,-1.6) 17(2.917,-1.2) 18(2.917,-0.8) 19(2.917,-0.4) 20(2.917,0) 21(2.917,0.4) 22(2.917,0.8) 23(2.917,1.2) 24(2.917,1.6) 25(2.917,2) 41(-2.918,2) 42(-2.918,1.6) 43(-2.918,1.2) 44(-2.918,0.8) 45(-2.918,0.4) 46(-2.918,0) 47(-2.918,-0.4) 48(-2.918,-0.8) 49(-2.918,-1.2) 50(-2.918,-1.6) 51(-2.918,-2)
  rect 3.4x3.4 smd: 53(0,0)
  Top Layer region: -2.817,2.5 -2.625,2.4 -2.625,2.3 -3.21,2.3 -3.21,2.5
  Top Layer region: -2.5,2.817 -2.4,2.625 -2.3,2.625 -2.3,3.21 -2.5,3.21
  Top Layer region: 2.5,2.818 2.4,2.625 2.3,2.625 2.3,3.21 2.5,3.21
  Top Layer region: 2.817,2.5 2.625,2.4 2.625,2.3 3.21,2.3 3.21,2.5
  Top Layer region: 2.817,-2.5 2.625,-2.4 2.625,-2.3 3.21,-2.3 3.21,-2.5
  Top Layer region: 2.5,-2.817 2.4,-2.625 2.3,-2.625 2.3,-3.21 2.5,-3.21
  Top Layer region: -2.817,-2.5 -2.625,-2.4 -2.625,-2.3 -3.21,-2.3 -3.21,-2.5
  Top Layer region: -2.5,-2.817 -2.4,-2.625 -2.3,-2.625 -2.3,-3.21 -2.5,-3.21
  silkscreen extent -3.08,-3.53 3.08,3.08
"r0201 nsk" [mil]
  rect 11.93x12.76 smd: 1(-9.51,0) 2(9.51,0)
R0402-NSK [mil]
  rect 19.68x22 smd: 1(-18,0) 2(18,0)
"R0603 NSK" [mil]
  rect 31.75x34.02 smd: 1(-29.66,0) 2(29.66,0)
RGBLED_0807 [mil]
  rect 35.83x70 smd: 1(-36,0) 2(37,0)
  silkscreen extent -6,-33 12,32
RJ45-TH_HR911130A [mil]
  round 66.9 hole 43.3: 11(260,272.6) 12(160,272.6) 13(-160,272.6) 14(-260,272.6)
  rect 60x60 hole 35.8: P1(229.6,-272.6)
  round 60 hole 35.8: P2(179.1,-172.4) P3(125.2,-272.4) P4(79.1,-172.4) P5(25.2,-272.4) P6(-20.9,-172.4) P7(-74.8,-272.4) P8(-120.9,-172.4) P9(-174.8,-272.4) P10(-220.9,-172.4)
  round 85 hole 65: SHIELD0(-315,-42.5) SHIELD1(315,-42.5)
  Multi-Layer board cut-out: -288.4,77.6 -282.06,49.83 -264.3,27.56 -238.64,15.2 -210.16,15.2 -184.5,27.56 -166.74,49.83 -160.4,77.6 -160.4,77.6 -166.74,105.36 -184.5,127.63 -210.16,139.99 -238.64,139.99 -264.3,127.64 -282.06,105.37 -288.4,77.6
  Multi-Layer board cut-out: 160.4,77.6 166.74,49.83 184.5,27.56 210.16,15.2 238.64,15.2 264.3,27.56 282.06,49.83 288.4,77.6 288.4,77.6 282.06,105.36 264.3,127.63 238.64,139.99 210.16,139.99 184.5,127.64 166.74,105.37 160.4,77.6
  Multi-Layer keep-out circle w10: c-224.4,77.6 r64
  Multi-Layer keep-out circle w10: c224.4,77.6 r64
  silkscreen extent -315,-347 315,503
SENSOR-SMD_IRM-H638T-TR2-TL [mm]
  rect 1.5x0.9 smd: 1(-2.95,1.27) 2(-2.95,-1.27) 3(2.95,-1.27) 4(2.921,1.27)
  silkscreen extent -2.99,-2.5 2,2.67
SIM-SMD_8P-1040310811 [mm]
  rect 0.7x1.2 smd: 1(3.138,-5.337) 2(2.037,-5.337) 3(0.938,-5.337) 4(-0.162,-5.337) 5(-1.263,-5.337) 6(-2.363,-5.337) 7(-3.462,-5.337) 8(-4.562,-5.337)
  rect 1.17x1.8 smd: 9(-5.773,-5.138)
  rect 1.55x1.35 smd: 10(5.598,-5.313)
  rect 1.2x1 smd: 11(5.773,0.663) 12(5.773,4.363)
  rect 1.9x1.35 smd: 13(2.273,5.337) 14(-3.697,5.337)
  silkscreen extent -6.07,-5.64 5.99,5.67
SLP2510P8_L2.5-W1.0-P0.50-BL [mm]
  rect 0.2x0.68 smd: 1(-1,-0.44) 2(-0.5,-0.44) 4(0.5,-0.44) 5(1,-0.44) 6(1,0.44) 7(0.5,0.44) 9(-0.5,0.44) 10(-1,0.44)
  rect 0.4x0.68 smd: 3(0,-0.44) 8(0,0.44)
  silkscreen extent -1.44,-0.88 1.3,0.55
SMA_L4.4-W2.8-LS5.4-R-RD [mil]
  rect 81.2x60.59 smd: 1(98.57,0) 2(-98.57,0)
  silkscreen extent -119,-56 104,56
SMC_L6.9-W5.9-LS7.9-BI [mm]
  rect 3.03x3.82 smd: 1(-3.435,0) 2(3.435,0)
  silkscreen extent -3.6,-3.11 3.6,3.11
